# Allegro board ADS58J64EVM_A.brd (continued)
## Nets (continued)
FMC_DIR_CONTROL: J3.H17 U3.15(IO_1_15)
FMC_SCLK: J3.C14 U3.2(IO_1_2/DIFFIO_L1P)
FMC_SDIO: J3.C15 U3.3(IO_1_3/DIFFIO_L1N)
FMC_SDO: J3.D14 U3.4(IO_1_4/DIFFIO_L2P)
FMC_SEN_ADC: J3.D15 U3.5(IO_1_5/DIFFIO_L2N)
FMC_SEN_LMK: J3.G15 U3.6(IO_1_6/DIFFIO_L3P)
FMC_SYSREF_N: C191.1 J3.K38
FMC_SYSREF_P: C190.1 J3.K37
FPGA_JESD_CLKM: C67.2 J3.D5
FPGA_JESD_CLKP: C68.2 J3.D4
FPGA_JESD_SYSREFM: J3.G10 R109.2
FPGA_JESD_SYSREFP: J3.G9 R108.2
FTDI_D5: U3.54(IO_2_54/DIFFIO_R7P) U7.9(D5)
FTDI_D6: U3.53(IO_2_53/DIFFIO_R7N) U7.10(D6)
FTDI_DIR_CONTROL: U3.52(IO_2_52) U7.6(D7)
FTDI_SCLK: U3.61(IO_2_61) U7.1(D0)
FTDI_SDIO: U3.58(IO_2_58/DIFFIO_R5P) U7.5(D1)
FTDI_SDO: U3.57(IO_2_57/DIFFIO_R5N) U7.3(D2)
FTDI_SEN_ADC: U3.56(IO_2_56/DIFFIO_R6P) U7.11(D3)
FTDI_SEN_LMK: U3.55(IO_2_55/DIFFIO_R6N) U7.2(D4)
IOVDD1.15V: C18.1 C19.1 C22.1 C53.1 C170.1 C272.1 C273.1 L3.2 R129.2 TP2.1(TP) U1.4(IOVDD#4) U1.51(IOVDD#51) U1.57(IOVDD#57) U1.64(IOVDD#64) U1.70(IOVDD#70)
JESD_CLKM: C68.1 U5.2(DCLKOUT0N)
JESD_CLKP: C67.1 U5.1(DCLKOUT0P)
JESD_SYSREFM: R108.1 U5.4(SDCLKOUT1N)
JESD_SYSREFP: R109.1 U5.3(SDCLKOUT1P)
LMK_CS: U3.78(IO_2_78/DIFFIO_T9P) U5.18(\\C\S\)
LMK_SCK: U3.77(IO_2_77/DIFFIO_T9N) U5.19(SCK)
LMK_SDIO: R134.2 U3.76(IO_2_76/DIFFIO_T10P) U5.20(SDIO)
LMK_SDO: R113.2 U5.5(RESET)
LMK_SYNC: J10.1(CENTER) R59.1 U5.6(SYNC)
OSCIN_N: C82.2 U5.44(OSCINN)
OSCIN_P: C92.2 C121.2 U5.43(OSCINP)
PDN: JP7.2(PIN2) U1.50(PDN)
RESET: R36.1 SW1.2 U1.48(RESET)
SCAN_EN: R19.2 R20.1 TP20.1(TP) U1.49(SCAN_EN)
SYNCBABM: J3.G13 U1.56(SYNCBABM)
SYNCBABP: J3.G12 U1.55(SYNCBABP)
SYNCBCDM: J3.H32 R185.2
SYNCBCDP: J3.H31 R186.2
SYSREF+: C190.2 R30.2 R133.1 U1.33(SYSREF_P)
SYSREF-: C191.2 R31.2 R133.2 U1.34(SYSREF_M)
SYSREF_N: C72.1 R44.1 U5.14(SDCLKOUT3N)
SYSREF_P: C73.1 R43.1 U5.13(SDCLKOUT3P)
SYSREFM: C73.2 R31.1 R106.1
SYSREFP: C72.2 R30.1 R105.1
T2_1: C141.2 R2.1 R3.1
T2_3: C140.2 R5.2 R6.1
T4_1: C158.2 R8.1 R9.1
T4_3: C157.2 R11.2 R12.1
T7_1: C274.2 R142.1 R144.1
T7_3: C275.2 R141.1 R143.2
T9_1: C203.2 R154.1 R155.1
T9_3: C202.2 R153.1 R156.2
TCK: J15.1 R57.1 U3.24(TCK)
TDI: J15.9 R110.1 U3.23(TDI)
TDO: J15.3 U3.25(TDO)
TMS: J15.5 R111.1 U3.22(TMS)
TRDYAB: J21.1 U1.54(TRDYAB)
TRDYCD: J22.1 U1.1(TRDYCD)
TRIGAB: J23.1 R170.1 U1.53(TRIGAB)
TRIGCD: J24.1 R173.1 U1.2(TRIGCD)
VCPLD1.8V: C155.2 C156.2 C162.2 C165.2 C166.2 C278.1 C279.1 C280.1 C281.1 C282.1 FB17.3 J15.4 JP3.1(PIN1) R110.2 R111.2 TP22.1(TP) U3.9(VCCIO1#9) U3.13(VCCINT#13) U3.31(VCCIO1#31) U3.45(VCCIO1#45) U3.63(VCCINT#63)
VSNS: R115.1 R117.1 U8.6(VSENSE)
N16275326: C10.2 T3.2(SECONDARY) T3.5(PRIMARY)
N16275564: C11.2 T4.2(SECONDARY) T4.5(PRIMARY)
N16918679: C81.2 C84.2 C85.2 C90.2 FB12.1 Y1.6(VDD)
N16918713: R78.2 R87.1 R88.1 Y1.5(OUT_P)
N16918734: R71.1 R73.2 R74.1 Y1.4(OUT_N)
N16918766: FB12.2 JP2.1
N16918796: C80.1 R71.2
N16918798: C80.2 C82.1 R77.1
N16918863: C92.1 C169.2 R61.2 R102.1
N16918987: SJP1.2(PIN2) Y1.2(NC)
N16974113: R113.1 U3.81(IO_2_81/DIFFIO_T8N)
N16976956: JP3.2(PIN2) U3.51(IO_1_51/DIFFIO_B10N)
N17045898: C169.1 R88.2
N17135362: C175.1 R104.1
N17316333: R60.2 R61.1
N17990226: C2.1 R3.2 R5.1
N18101124: Q1.4(G) U12.4(GATE)
N18135910: C106.1 C107.1 C108.1 C109.1 C148.1 FB15.1 R45.1 U11.1(OUT1) U11.2(OUT2)
N18153199: C95.1 J13.2(D-) U7.16(USBDM)
N18153225: C91.1 C163.1 FB10.1 R96.2 TP21.1(TP) U7.20(VCC)
N18153227: C99.1 U7.4(VCCIO) U7.17(3V3OUT)
N18153268: C93.1 J13.3(D+) U7.15(USBDP)
N18164060: J13.4(ID) R13.2
N18272382: C137.1 C138.1 C139.1 C182.1 FB14.1 R123.1 U2.1(OUT1) U2.2(OUT2)
N18340257: D2.1(ANODE) R41.2
N18400299: D1.1(ANODE) R91.1
N18433453: R112.2 R114.1 U8.15(EN)
N18433599: C135.1 R52.1 U8.7(COMP)
N18433651: C144.1 R52.2
N18433655: R51.1 U8.8(RT/CLK)
N18433661: C136.1 U8.9(SS/TR)
N18433720: R118.1 U8.14(PWRGD)
N18433762: C124.1 L1.1 U8.10(PH1) U8.11(PH2) U8.12(PH3)
N18433788: C124.2 U8.13(BOOT)
N18529139: J3.C18 R91.2
N18529232: J3.H2 R84.1
N18993446: C8.1 R9.2 R11.1
N19018410: R18.2 SW1.1
N19072087: FB10.2 J13.1(VBUS)
N19596618: D6.1(ANODE) R85.1
N19596621: D5.1(ANODE) R82.1
N19596623: D3.1(ANODE) R86.1
N19596624: R86.2 U5.48(STATUS_LD2)
N19596626: R85.2 U5.31(STATUS_LD1)
N19596640: C88.1 U5.12(LDOBYP2)
N19596641: C87.1 U5.11(LDOBYP1)
N19596650: D4.1(ANODE) R81.1
N19596653: R82.2 U5.59(CLKIN_SEL1)
N19596656: R81.2 U5.58(CLKIN_SEL0)
N19631315: C74.1 C76.1 C150.1 C151.1 FB16.1 U6.1(OUT1) U6.3(SENSE) U6.20(OUT2)
N19631466: C98.1 U6.14(NR)
N19631491: R83.2 U6.8(1P6V)
N19631493: R75.2 U6.11(0P2V)
N19631495: R72.2 U6.12(0P1V)
N19631505: R76.2 U6.10(0P4V)
N19740812: C183.1 U2.6(NR)
N19741196: R125.2 R126.1 U2.5(EN)
N19751506: C49.1 T5.5(GND)
N19764898: C137.2 R124.1 R176.2 U2.3(FB/SNS)
N19785823: C3.2 R63.2
N19785833: C3.1 R101.1
N19786108: C9.2 R107.2
N19786128: C9.1 R119.1
N19791732: C158.1 T4.4(PRIMARY_DOT)
N19791735: C157.1 T4.6(PRIMARY_CT)
N19818342: C123.1 C127.1 C128.1 C129.1 C263.1 FB13.1 R50.1 U10.1(OUT1) U10.2(OUT2)
N19818462: C134.1 U10.6(NR)
N19818472: R161.2 R162.1 U10.5(EN)
N19818541: C129.2 R116.1 R174.2 U10.3(FB/SNS)
N19839460: R28.2 R29.1 U15.1(EN)
N19839464: C195.1 L2.2 R28.1 U15.7(VIN)
N19839484: L4.1 U15.6(SW)
N19839486: C196.1 R33.2 R37.1 U15.4(VOS)
N19839498: C197.1 C198.1 C271.1 L3.1 L4.2 R33.1
N19839502: C196.2 R32.1 R37.2 U15.3(FB)
N19884960: C201.1 R143.1 R144.2
N19885012: C274.1 T7.4(PRIMARY_DOT)
N19885116: C276.2 R145.2
N19885138: C276.1 R146.1
N19885156: C277.2 T6.2(SECONDARY) T6.5(PRIMARY)
N19885198: C200.2 T7.2(SECONDARY) T7.5(PRIMARY)
N19885294: C203.1 T9.4(PRIMARY_DOT)
N19885373: C206.1 R155.2 R156.1
N19885375: C204.2 T8.2(SECONDARY) T8.5(PRIMARY)
N19885421: C205.2 T9.2(SECONDARY) T9.5(PRIMARY)
N19885585: C207.2 R157.2
N19885597: C207.1 R158.1
N19895674: R182.2 R183.1 R186.1 U1.72(SYNCBCDP)
N19895681: R182.1 R184.2 R185.1 U1.71(SYNCBCDM)
N19922962: C141.1 T2.4(PRIMARY_DOT)
N19926392: C4.2 T1.2(SECONDARY) T1.5(PRIMARY)
N19927040: C5.2 T2.2(SECONDARY) T2.5(PRIMARY)
N19928466: C202.1 T9.6(PRIMARY_CT)
N19936516: C140.1 T2.6(PRIMARY_CT)
N19989779: C275.1 T7.6(PRIMARY_CT)
N20022529: R50.2 R174.1
N20035911: R123.2 R176.1
N20038291: C265.1 U9.15(SS)
N20038313: R166.2 R167.1 U9.11(EN)
N20038327: R64.2 R175.1
N20038329: R128.1 R175.2 U9.16(FB/SNS)
N20038355: C115.1 C116.1 C117.1 R64.1 R129.1 U9.1(OUT4) U9.18(OUT1) U9.19(OUT2) U9.20(OUT3)
N20039194: C286.1 U16.6(NR)
N20039222: R177.2 R178.1 U16.5(EN)
N20039339: C283.1 C284.1 C285.1 C287.1 FB17.1 R180.1 U16.1(OUT1) U16.2(OUT2)
N20039347: C287.2 R180.2 R181.1 U16.3(FB/SNS)
N20052215: C290.1 T5.2(PRIMARY)
N20058798: C184.1 R187.2 U9.10(BIAS)
N20074843: C114.1 U11.6(NR)
N20074851: R188.2 R189.1 U11.5(EN)
N20074920: C106.2 R47.2 R48.1 U11.3(FB/SNS)
N20074982: R45.2 R47.1
N195971120: C66.2 R65.1
N195974181: C65.2 R66.1

Pads without a net: J3 A14 A15 A18 A19 A22 A23 A26 A27 A30 A31 A34 A35 A38 A39 B1 B4 B5 B8 B9 B12 B13 B16 B17 B20 B21 B24 B25 B28 B29 B32 B33 B36 B37 B40 C2 C3 C10 C11 C19 C22 C23 C26 C27 C30 C31 C34 C35 C37 C39 D1 D8 D9 D11 D12 D17 D18 D20 D21 D23 D24 D26 D27 D29 D30 D31 D32 D33 D34 D35 D36 D38 D40 E2 E3 E6 E7 E9 E10 E12 E13 E15 E16 E18 E19 E21 E22 E24 E25 E27 E28 E30 E31 E33 E34 E36 E37 E39 F1 F4 F5 F7 F8 F10 F11 F13 F14 F16 F17 F19 F20 F22 F23 F25 F26 F28 F29 F31 F32 F34 F35 F37 F38 F40 G2 G3 G18 G19 G21 G22 G24 G25 G27 G28 G30 G31 G33 G34 G36 G37 G39 H1 H4 H5 H7 H8 H10 H11 H13 H14 H19 H20 H22 H23 H25 H26 H28 H29 H34 H35 H37 H38 H40 J2 J3 J6 J7 J9 J10 J12 J13 J15 J16 J18 J19 J21 J22 J24 J25 J27 J28 J30 J31 J33 J34 J36 J37 J39 K1 K4 K5 K7 K8 K10 K11 K13 K14 K16 K17 K19 K20 K22 K23 K25 K26 K31 K32 K34 K35 K40; J15 6 7 8; NOREF#9 1; NOREF#13 1; NOREF#16 1; NOREF#31 1; NOREF#35 1; NOREF#36 1; NOREF#37 1; T5 1; U1 22 23; U3 12 14 16 17 18 19 20 21 26 27 28 29 30 37 38 39 40 41 42 43 44 47 48 49 50 62 64 66 67 68 69 70 71 72 73 74 75 82 83 84 85 86 87 88 89 90 91 92 95 96 97 98 99 100; U5 7 8 9 22 23 24 25 27 28 29 30 37 38 40 41 49 50 51 52 54 55 56 57 60 61; U6 2 4 5 6 9 17 18 19; U7 8 12 13 14 19 22 23 24 27 28; U9 9; U12 1 3; U15 2

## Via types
v1: diameter 0.457, hole 0.203, TOP to BOTTOM, 602 vias
v2: diameter 0.356, hole 0.152, TOP to BOTTOM, 82 vias
v3: diameter 0.508, hole 0.254, TOP to BOTTOM, 2773 vias
v4: diameter 0.559, hole 0.305, TOP to BOTTOM, 281 vias
v5: diameter 0.762, hole 0.381, TOP to BOTTOM, 8 vias
v6: diameter 0.4, hole 0.203, TOP to BOTTOM, 48 vias

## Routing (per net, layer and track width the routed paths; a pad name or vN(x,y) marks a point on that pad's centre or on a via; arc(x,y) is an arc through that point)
5.0V_IN: length 24.6
  BOTTOM w0.127: Q1.8 19.41,62.61 v4(19.51,62.71) ; v4(20.53,60.72) 20.51,60.74 v4(20.51,61.71) ; v4(20.53,60.72) 20.54,60.71 v4(21.51,60.71) ; v4(20.53,60.72) 19.52,60.72 v4(19.51,60.71) ; v4(20.53,60.72) 20.53,59.73 v4(20.51,59.71) ; v4(21.51,60.71) v4(21.51,59.71) ; v4(21.51,60.71) v4(21.51,61.71) ; v4(19.51,62.71) v4(19.51,61.71) ; v4(19.51,62.71) v4(20.51,62.71) ; v4(21.51,59.71) v4(20.51,59.71) ; v4(21.51,59.71) v4(21.51,58.71) v4(20.51,58.71) ; v4(19.51,61.71) v4(20.51,61.71) ; v4(19.51,61.71) v4(19.51,60.71) ; v4(20.51,58.71) v4(19.51,58.71) ; v4(20.51,58.71) v4(20.51,59.71) ; v4(19.51,58.71) v4(19.51,59.71) ; v4(19.51,58.71) 19.41,58.8 Q1.5 ; v4(21.51,61.71) v4(20.51,61.71) ; v4(21.51,61.71) v4(21.51,62.71) v4(20.51,62.71) ; v4(20.51,61.71) v4(20.51,62.71) ; v4(20.51,59.71) v4(19.51,59.71) ; v4(19.51,59.71) v4(19.51,60.71)
5VIN: length 6
  TOP w0.254: U8.16 8.99,90.89 v3(8.75,90.65)
  TOP w0.305: v4(8.69,73.23) 8.85,73.06 U6.16 ; v3(9.8,88.87) 10.34,89.41 U8.2 ; U6.15 7.34,74.16 v4(6.4,73.23)
  TOP w0.356: U6.13 v3(6.58,75.46)
  vias: v3(5.74,93.45) v3(5.82,89.1) v3(5.82,87.83) v3(5.82,86.44) v3(5.82,85.17) v3(5.82,83.9) v3(6.71,88.47) v3(6.71,87.07) v3(6.71,85.8) v3(6.71,84.53) v3(6.71,83.26) v3(7.34,90.25) v3(7.85,88.72) v3(7.85,87.45) v3(7.85,86.31) v3(7.9,84.81) v3(7.9,83.29) v3(8.66,84.05) v3(8.74,89.36) v3(8.74,85.67) v3(8.99,86.82) v3(9.12,88.09) v3(9.3,84.81) v3(9.3,83.29) v3(9.84,90.45) v3(10.13,87.83) v3(10.08,86.72) v3(10.08,85.57) v3(20.88,41.22) v3(20.88,40.08) v3(20.88,39.07) v3(22.22,41.15) v3(22.22,40.01) v3(22.22,38.99) v3(23.49,41.15) v3(23.49,40.01) v3(23.49,38.99) v4(6.4,72.09) v4(6.4,70.94) v4(7.54,73.23) v4(7.54,72.09) v4(7.54,70.94) v4(8.69,72.09) v4(8.69,70.94) v4(23.52,64.9) v4(23.52,63.63) v4(23.52,62.36) v4(23.52,61.21) v4(23.52,60.07) v4(24.64,64.9) v4(24.64,63.63) v4(24.64,62.36) v4(24.64,61.21) v4(24.64,60.07) v4(25.91,62.36) v4(25.91,61.21) v4(25.91,60.07) v4(27.05,62.36) v4(27.05,61.21) v4(27.05,60.07) v4(28.19,62.36) v4(28.19,61.21) v4(28.19,60.07) v4(31.06,75.23) v4(31.06,73.96) v4(31.06,72.69) v4(31.06,71.55) v4(31.09,70.38) v4(32.18,75.23) v4(32.18,73.96) v4(32.18,72.69) v4(32.18,71.55) v4(32.21,70.38)
+2.5V: length 19.1
  TOP w0.305: v3(37.56,64.48) v3(35.46,64.48) 35.12,64.48 35.03,64.39 35.59,63.83 37.56,63.83 ; U9.5 56.88,81.34 C185.1 ; v3(31.9,96.56) v3(29.79,96.56) 29.45,96.56 29.36,96.47 C126.1 29.92,95.91 31.9,95.91 ; U2.8 28.02,87.5 C288.1 27.55,88.15 v3(27.89,88.15) v3(29.99,88.15) ; U11.7 30.69,106.61 v3(30.6,106.52)
  vias: v3(9.07,107.11) v3(9.07,105.97) v3(10.57,107.11) v3(10.57,105.97) v3(12.01,107.09) v3(12.01,105.94) v3(15.67,87.6) v3(16.66,99.87) v3(16.69,102.16) v3(16.69,101.02) v3(17.65,102.16) v3(17.65,101.02) v3(17.63,99.87) v3(18.64,102.13) v3(18.64,100.99) v3(18.62,99.85) v3(19.66,99.87) v3(19.68,102.16) v3(19.68,101.02) v3(20.68,99.87) v3(20.7,102.16) v3(20.7,101.02) v3(21.67,102.16) v3(21.67,101.02) v3(21.64,99.87) v3(26.8,88.16) v3(26.8,87.02) v3(26.8,85.83) v3(27.86,85.83) v3(27.89,87.02) v3(28.7,96.57) v3(28.7,95.43) v3(28.7,94.23) v3(28.93,88.1) v3(28.93,86.97) v3(28.91,85.83) v3(29.4,106.52) v3(29.4,105.45) v3(29.4,104.41) v3(29.4,103.34) v3(29.77,94.23) v3(29.79,95.43) v3(29.97,85.83) v3(30,87.02) v3(30.55,104.38) v3(30.6,105.43) v3(30.6,103.32) v3(30.83,96.51) v3(30.84,95.38) v3(30.81,94.23) v3(31.73,105.43) v3(31.68,104.39) v3(31.7,103.33) v3(31.9,95.43) v3(31.88,94.23) v3(34.37,64.49) v3(34.37,63.35) v3(34.37,62.15) v3(35.46,63.35) v3(35.43,62.15) v3(36.47,62.15) v3(36.5,64.43) v3(36.5,63.3) v3(37.57,63.35) v3(37.54,62.15) v3(47.55,81.46) v3(51.77,85.9) v3(53.52,84.76) v3(53.52,83.62) v3(53.52,82.42) v3(54.61,84.75) v3(54.61,83.62) v3(54.58,82.42) v3(55.65,84.7) v3(55.65,83.57) v3(55.63,82.42) v3(56.72,84.75) v3(56.72,83.62) v3(56.69,82.42)
+3.3VCLK: length 10.3
  TOP w0.305: v3(48.69,44.4) 48.39,44.1 U3.94
  TOP w0.318: v3(41.49,44.36) 41.41,44.02 41.39,44.01 41.39,42.77 U3.80 ; U3.59 v3(39.1,52.47)
  TOP w0.508: R134.1 75.95,59.69 v3(75.44,60.2)
  BOTTOM w0.508: C153.2 v3(48.69,45.03) ; C152.2 v3(41.48,45.09) ; v3(39.1,52.47) v3(39.1,53.14)
  vias: v3(20.75,73.3) v3(20.75,70.92) v3(20.78,75.69) v3(20.83,74.52) v3(22.33,75.72) v3(22.35,74.52) v3(22.63,73.33) v3(22.73,70.92) v3(23.77,75.74) v3(23.8,74.57) v3(23.85,73.33) v3(23.88,72.14) v3(23.83,70.92) v3(25.07,74.57) v3(25.07,70.94) v3(25.1,75.74) v3(25.12,73.33) v3(25.1,72.16) v3(73.56,51.87) v3(73.53,50.62) v3(73.79,62.87) v3(73.79,60.2) v3(73.79,57.53) v3(74.55,62.74) v3(74.55,51.87) v3(74.55,50.65) v3(74.93,59.82) v3(75.06,57.02) v3(75.44,62.87) v3(75.44,57.53) v3(75.51,51.84) v3(75.49,50.65) v3(75.82,63.5) v3(75.82,58.17) v3(96.06,66) v3(96.6,65.19) v3(97.13,66) v3(98.22,65.35) v3(100.71,44.95) v3(100.71,40.28) v3(101.78,55.02) v3(101.96,56.41) v3(102.57,55.63) v3(103.05,56.46) v3(103.4,55.25) v3(104.29,55.68) v3(105,52.3) v3(105,51.26) v3(105.05,50.27) v3(105.05,49.23) v3(106.02,52.32) v3(106.02,51.26) v3(106.07,50.29) v3(106.07,49.23) v3(120.32,41.34)
AVDD1.9V: length 96.5
  TOP w0.241: v1(105.89,85.09) 106.25,85.09 v2(106.43,84.91) v2(106.99,84.91) ; v1(117.98,85.14) 117.5,85.14 v2(117.39,85.03) 117.27,84.91 v2(116.79,84.91) ; v1(105.89,81.58) 106.21,81.58 v2(106.46,81.83) 106.47,81.83 106.55,81.91 U1.45 v2(107.01,81.91) ; v1(109.98,87.66) 110.13,87.5 v2(110.13,87.12) v2(110.13,86.56) ; v1(113.77,87.66) 113.64,87.53 v2(113.64,86.56)
  TOP w0.254: v2(116.79,81.91) 117.29,81.91 117.53,82.14 v1(117.98,82.14)
  L3-PWR1 w0.508: JP7.1 167.23,79.88 170.15,76.96 170.15,72.92 165.15,67.92 v1(162.28,67.92)
  L6-PWR2 w0.127: v1(105.89,81.58) 106.22,81.58 106.55,81.91 106.56,81.91 v2(107.01,81.91)
  L6-PWR2 w0.508: 100.66,81.74 100.66,80.67 99.92,79.93 v1(98.32,79.93) ; v1(119.74,80.04) 122.07,80.04 ; 122.07,80.04 155.88,80.04 158.78,82.93 164.08,82.93 JP7.1 ; 122.07,80.04 122.1,80.01 122.1,78.41 121.51,77.83 121.51,75.97 120.6,75.06 119.56,75.06 v1(118.01,73.51)
  BOTTOM w0.254: v1(109.98,87.66) 110.13,87.5 v2(110.13,87.12) v2(110.13,86.56) ; v2(107.01,81.91) 106.54,81.91 v2(106.46,81.83) 106.21,81.58 v1(105.89,81.58) ; v1(117.98,82.14) 117.53,82.14 v2(117.38,81.99) 116.87,81.99 v2(116.79,81.91) ; v1(105.89,85.09) 106.07,84.91 v2(106.43,84.91) v2(106.99,84.91) ; v2(113.64,86.56) 113.64,86.57 v2(113.64,87.13) 113.77,87.25 v1(113.77,87.66) ; v2(116.79,84.91) 117.27,84.91 v2(117.39,85.03) 117.5,85.14 v1(117.98,85.14)
  vias: v1(44.7,108.51) v1(44.73,107.42) v1(44.73,106.4) v1(44.73,105.38) v1(44.73,104.37) v1(44.73,103.35) v1(45.72,108.51) v1(45.75,107.42) v1(45.75,106.4) v1(45.75,105.38) v1(45.75,104.37) v1(45.75,103.35) v1(46.74,108.51) v1(46.81,107.39) v1(46.81,106.38) v1(47.75,108.51) v1(47.83,107.39) v1(47.83,106.38) v1(48.77,108.51) v1(48.84,107.39) v1(48.84,106.38)
AVDD1.15V: length 31.4
  TOP w0.241: v1(105.89,85.7) 106.32,85.7 106.61,85.41 v2(106.99,85.41) ; v2(115.64,86.56) v2(115.64,87.21) v1(116.01,87.59) ; v2(117.37,82.91) v2(116.79,82.91) ; v2(106.99,82.91) 106,82.91 v1(105.89,82.8) ; v1(105.89,82.19) 106.2,82.19 v2(106.41,82.41) v2(106.99,82.41) ; v2(116.79,81.41) 117.43,81.41 ; v2(108.14,86.56) v2(108.14,87.16) v1(107.71,87.59) ; v2(116.79,85.41) 117.16,85.41 117.5,85.75 v1(117.98,85.75) ; v1(113.03,87.66) 113.14,87.55 v2(113.14,86.56) ; v1(110.74,87.66) 110.64,87.55 v2(110.64,86.56) ; v1(105.89,80.98) 106.2,80.98 106.63,81.41 v2(106.99,81.41) ; v2(116.79,84.41) 117.86,84.41 v1(117.98,84.53) ; v2(106.99,84.41) 105.96,84.41 v1(105.89,84.48)
  TOP w0.254: v1(117.98,82.75) 117.83,82.91 v2(117.37,82.91) ; v1(117.98,81.53) 117.56,81.53 v2(117.43,81.41) 117.43,81.41
  BOTTOM w0.254: v1(117.98,85.75) 117.51,85.75 v2(117.38,85.62) 117,85.62 v2(116.79,85.41) ; v2(116.79,84.41) 116.79,84.4 v2(117.38,84.4) 117.86,84.4 v1(117.98,84.53) ; v1(105.89,84.48) 105.96,84.41 v2(106.42,84.41) 106.42,84.41 v2(106.99,84.41) ; v2(110.64,86.56) 110.64,87.12 v2(110.63,87.13) 110.63,87.54 v1(110.74,87.66) ; v2(116.79,82.91) 117.37,82.91 v2(117.37,82.91) 117.82,82.91 v1(117.98,82.75) ; v2(106.99,82.41) v2(106.41,82.41) 106.11,82.41 v1(105.89,82.19) ; v2(106.99,82.91) 106.43,82.91 v2(106.42,82.9) 105.99,82.9 v1(105.89,82.8) ; v2(113.14,86.56) 113.14,87.15 v2(113.13,87.16) 113.13,87.55 v1(113.03,87.66) ; v2(108.14,86.56) v2(108.14,87.16) v1(107.71,87.59) ; v2(106.99,81.41) 106.65,81.41 106.22,80.98 v1(105.89,80.98) ; v1(117.98,81.53) 117.56,81.53 v2(117.43,81.41) 117.43,81.41 v2(116.79,81.41) ; v1(105.89,85.7) 106.32,85.7 v2(106.42,85.6) 106.8,85.6 v2(106.99,85.41) ; v1(116.01,87.59) v2(115.64,87.21) v2(115.64,86.56)
  vias: v1(43.18,97.71) v1(43.18,96.67) v1(43.18,95.53) v1(43.21,94.34) v1(43.18,93.17) v1(44.12,97.71) v1(44.12,96.67) v1(44.12,95.53) v1(45.36,97.69) v1(45.36,96.65) v1(45.36,95.5) v1(46.3,97.69) v1(46.3,96.65) v1(46.3,95.5) v1(47.35,97.69) v1(47.35,96.65) v1(47.35,95.5) v1(47.35,94.34) v1(47.35,93.19) v1(48.29,97.69) v1(48.29,96.65) v1(48.29,95.5) v1(48.29,94.34) v1(48.29,93.19) v2(106.42,81.21)
GND: length 170.7
  TOP w0.241: v1(110.11,75.69) 110.14,75.72 v1(110.14,76.23) v2(110.14,76.76) ; v1(113.66,75.69) 113.64,75.72 v1(113.64,76.23) v2(113.64,76.76) ; v2(111.64,76.76) v2(111.63,76.33)
  TOP w0.254: v2(111.14,86.56) v2(111.14,87.14) ; v2(115.14,86.56) v2(115.14,87.15) ; v2(109.64,86.56) v2(109.65,87.12) ; v2(106.53,78.41) v2(106.99,78.41) ; v2(112.64,86.56) v2(112.65,87.12)
  TOP w0.305: v3(38.79,49.48) U3.65 v3(36.6,49.48) ; v3(113.74,72.57) 113.63,72.68 113.63,75.66 v1(113.66,75.69) ; v3(48.39,56.97) U3.32 v3(48.39,59.38) 48.39,59.39 ; v4(33.88,97.64) 34.25,98.01 U10.4 ; 118.03,77.87 117.49,78.41 v2(117.27,78.41) v2(116.79,78.41) ; 115.44,73.59 116.18,72.85 v3(116.18,72.59) ; v3(54.38,49.5) 54.35,49.47 U3.11 51.73,49.47 v3(51.56,49.3) ; v3(39.01,51.69) 38.73,51.97 U3.60 v3(36.6,51.97) ; 33.05,95.73 v3(33.05,94.84) ; v1(110.11,75.69) 110.11,70.28 v3(110.52,69.88) ; U3.10 54.33,48.97 v3(54.38,48.92) ; v3(40.89,41.41) U3.79 40.89,43.92 v3(40.46,44.35) ; U8.4 11.34,90.03 v3(11.1,89.79) 10.84,90.05 U8.3 ; v4(39.54,65.62) 39.92,66 U16.4 ; U6.7 v3(10.91,78.75) ; 32.87,108.33 32.87,108.81 32.64,109.04 C114.2 33.3,110.06 33.48,109.88 33.48,108.51 ; C22.2 v3(111.86,73.51) ; v3(51.92,44.37) 52.01,44.47 U3.1 53.88,44.47 v3(54.23,44.12) ; U9.12 v3(50,80.69) ; 33.05,98.43 33.05,98.91 32.66,99.29 C134.2 32.74,100.05 33.35,100.05 33.71,99.69 33.71,98.32 ; 33.71,95.73 v3(33.71,94.84) ; 31.14,90.02 31.14,91.19 C183.2 31.52,91.41 31.78,91.16 31.78,90.14 ; v3(41.4,59.36) U3.46 41.39,56.73 v3(41.17,56.52) ; 12.19,91.3 v3(12.19,90.98) ; v2(106.53,78.41) 106.53,78.41 105.67,78.41 105.41,78.66 ; U9.3 v3(56.77,80.04) ; v4(31.97,89.08) 32.34,89.45 U2.4 ; U9.2 v3(56.78,79.39) ; v4(33.67,107.53) 34.05,107.91 U11.4 ; 38.68,63.63 v3(38.68,62.94) ; v3(47.68,44.27) 47.89,44.06 U3.93 v3(47.89,41.41) ; U9.17 v3(52.72,76.69) ; 39.4,66.37 39.4,67.72 38.94,68.17 38.4,68.17 C286.2 38.33,67.31 38.73,66.9 38.73,66.37 ; v1(118.36,78.92) 118.36,78.41 118.38,78.4 ; 39.37,63.6 v3(39.37,62.87) ; 31.14,87.1 v3(31.14,86.26) ; U9.4 v3(56.73,80.69) ; 31.8,87.05 v3(31.8,86.26)
  TOP w0.356: U9.14 49.57,79.39 v3(49.2,79.76) 49.48,80.04 U9.13
  TOP w0.508: 105.83,63.71 106.08,63.71 106.81,62.97 107.58,62.97 v3(107.82,63.22) ; 42.44,76.84 42.44,77.57 v3(42.11,77.9) ; v3(41.07,77.93) 41.2,77.8 C197.2
  BOTTOM w0.254: v2(116.79,78.41) v2(117.27,78.41)
  BOTTOM w0.305: v3(38.33,78.54) U15.5 37.84,78.04 v3(38.22,77.66) ; v3(48.39,56.97) 48.11,56.69 C165.1 48.11,56.54 v3(48.36,56.29)
  BOTTOM w0.356: v3(22.79,48.09) U7.21 24.71,48.09 v3(24.71,48.08) ; v3(24.74,50.7) 24.73,50.69 U7.25 22.72,50.69 v3(22.71,50.67) ; v3(32.05,48.74) U7.7 v3(29.82,48.72) ; U7.18 22.79,46.14 v3(22.78,46.13) ; v3(22.71,51.36) 22.73,51.34 U7.26 24.71,51.34 v3(24.71,51.33)
  BOTTOM w0.508: J3.B7 J3.A8 J3.A9 ; J3.A9 J3.B10 J3.B11 149.1,8.76 v1(147.83,8.76) 146.56,10.03 J3.B15 v1(144.02,8.76) ; J3.A9 v1(152.3,8.15) ; v1(142.75,13.84) v1(144.02,12.57) J3.C16 v1(142.75,11.3) v1(141.48,10.03) ; v1(142.75,13.84) v1(141.48,15.11) v1(142.75,16.38) ; v1(142.75,13.84) v1(143.33,14.43) ; v1(157.99,16.38) 156.72,17.65 v1(157.99,18.92) ; 156.72,20.19 156.79,20.19 v3(157.51,20.9) ; v1(133.86,20.19) 133.86,20.17 v1(133.32,19.63) ; J3.J23 v1(135.13,18.87) v1(134.57,18.31) ; C164.2 v3(88.75,52.45) ; v3(150.32,21.41) 149.1,20.19 v1(150.37,18.92) 149.1,17.65 v1(150.37,16.38) 149.1,15.11 v1(150.37,13.84) 151.64,12.57 ; v1(137.67,15.11) 138.94,16.38 v1(137.67,17.65) v1(138.94,18.92) v1(137.67,20.19) 137.69,20.19 v3(138.51,21.01) ; C88.2 86.11,61.85 v3(86.49,61.47) ; J3.G8 v1(152.91,17.65) ; 149.1,11.3 v1(147.83,11.3) ; 156.72,15.11 v1(157.99,13.84) 156.72,12.57 ; J3.B3 v1(159.26,11.3) ; v1(141.48,17.65) v1(142.75,18.92) ; v1(152.91,15.11) J3.E8 155.45,12.57 ; J3.J8 v1(152.91,20.19) ; 156.72,10.03 v1(157.99,11.3) ; v1(152.91,11.3) J3.C8 ; C87.2 v3(87.5,61.47) ; J3.B2 v1(163.07,8.76)
  vias: v1(86.61,69.09) v1(90.04,69.09) v1(99.69,81.03) v1(105.28,85.7) v1(105.28,85.09) v1(105.28,84.48) v1(105.28,82.8) v1(105.28,82.19) v1(105.28,81.58) v1(105.28,80.98) v1(105.28,80.37) v1(105.46,78.89) v1(107.28,88.02) v1(108.43,75.03) v1(109.98,88.27) v1(110.74,88.27) v1(113.03,88.27) v1(113.54,18.92) v1(113.54,16.38) v1(113.54,13.84) v1(113.54,11.3) v1(113.54,8.76) v1(113.77,88.27) v1(114.81,20.19) v1(114.81,17.65) v1(114.81,15.11) v1(114.81,12.57) v1(114.81,10.03) v1(115.32,75.11) v1(116.13,73.51) v1(116.08,18.92) v1(116.08,16.38) v1(116.08,13.84) v1(116.08,11.3) v1(116.08,10.03) v1(116.45,88.02) v1(117.35,12.57) v1(117.35,8.76) v1(118.59,85.75) v1(118.59,85.14) v1(118.59,84.53) v1(118.59,82.75) v1(118.59,82.14) v1(118.59,81.53) v1(118.59,80.92) v1(118.62,20.19) v1(118.62,17.65) v1(118.62,15.11) v1(118.62,11.3) v1(118.62,8.76) v1(119.89,18.92) v1(119.89,16.38) v1(119.89,13.84) v1(119.89,10.03) v1(121.16,10.03) v1(122.43,20.19) v1(122.43,17.65) v1(122.43,15.11) v1(122.43,11.3) v1(122.43,8.76) v1(123.7,18.92) v1(123.7,16.38) v1(123.7,13.84) v1(123.7,11.3) v1(123.7,8.76) v1(124.97,10.03) v1(126.24,20.19) v1(126.24,17.65) v1(126.24,15.11) v1(126.24,10.03) v1(127.51,18.92) v1(127.51,16.38) v1(127.51,13.84) v1(127.51,11.3) v1(127.51,8.76) v1(128.78,12.57) v1(128.78,11.3) v1(128.78,8.76) v1(130.05,20.19) v1(130.05,17.65) v1(130.05,15.11) v1(130.05,10.03) v1(131.32,18.92) v1(131.32,16.38) v1(131.32,13.84) v1(131.32,10.03) v1(132.38,82.68) v1(132.59,12.57) v1(132.59,11.3) v1(132.59,8.76) v1(133.86,17.65) v1(133.86,15.11) v1(133.86,11.3) v1(133.86,8.76) v1(135.13,16.38) v1(135.13,13.84) v1(135.13,10.03) v1(136.4,12.57) v1(136.4,10.03) v1(136.68,84.68) v1(137.67,11.3) v1(137.67,8.76) v1(138.94,13.84) v1(138.94,11.3) v1(138.94,8.76) v1(140.21,12.57) v1(140.21,10.03) v1(141.48,20.19) v1(142.75,8.76) v1(145.29,20.19) v1(145.29,17.65) v1(145.29,15.11) v1(146.56,18.92) v1(146.56,16.38) v1(146.56,13.84) v1(147.83,12.57) v1(149.79,8.38) v1(151,9) v1(151.77,8.06) v1(154.93,8.32) v1(155.09,11.88) v1(156.08,11.04) v1(156.08,9.14) v1(157.25,8.33) v1(157.29,11.69) v1(157.28,9.24) v1(157.99,8.76) v1(159.26,18.92) v1(159.26,16.38) v1(159.26,13.84) v1(159.26,8.76) v1(160.08,8.26) v1(160.53,20.19) v1(160.53,17.65) v1(160.53,15.11) v1(160.53,12.57) v1(161.16,8.4) v1(161.8,20.19) v1(161.8,15.11) v1(161.8,12.57) v1(162.28,8.26) v1(163.07,18.92) v1(163.07,16.38) v1(163.07,13.84) v1(163.07,11.3) v2(117.73,78.18) v3(0.64,112.4) v3(0.64,109.85) v3(0.64,107.31) v3(0.64,104.78) v3(0.64,102.24) v3(0.64,99.69) v3(0.64,97.16) v3(0.64,94.62) v3(0.64,92.08) v3(0.64,89.53) v3(0.64,87) v3(0.64,84.46) v3(0.64,81.91) v3(0.66,46.69) v3(0.66,44.15) v3(0.66,41.61) v3(0.66,39.07) v3(0.69,79.45) v3(0.69,76.91) v3(0.69,74.37) v3(0.69,71.83) v3(0.69,69.29) v3(0.69,66.75) v3(0.69,64.21) v3(0.69,61.67) v3(0.69,59.13) v3(0.69,56.59) v3(0.69,54.05) v3(0.69,51.51) v3(0.69,48.97) v3(1.52,40.13) v3(1.52,38.86) v3(1.65,49.02) v3(1.65,47.75) v3(1.91,113.03) v3(2.38,39.5) v3(2.51,48.39) v3(2.54,43.87) v3(2.67,94.49) v3(2.67,91.95) v3(2.67,89.41) v3(2.67,86.87) v3(2.74,84.53) v3(3.3,40.13) v3(3.3,38.86) v3(3.43,49.02) v3(3.43,47.75) v3(3.56,61.7) v3(3.56,59.13) v3(3.53,56.85) v3(3.81,113.03) v3(3.81,54.64) v3(3.84,50.47) v3(3.94,104.65) v3(3.94,102.11) v3(3.94,99.57) v3(3.94,97.03) v3(3.94,81.79) v3(3.94,79.25) v3(3.89,74.81) v3(3.94,72.9) v3(3.94,70.36) v3(4.67,77.37) v3(4.67,76.23) v3(5.08,43.87) v3(5.21,52.58) v3(5.31,106.83) v3(5.77,90.23) v3(6.35,113.03) v3(6.35,69.34) v3(6.35,54.64) v3(6.38,50.47) v3(6.48,104.65) v3(6.48,102.11) v3(6.48,99.57) v3(6.48,97.03) v3(6.48,81.79) v3(6.48,79.25) v3(6.88,41.12) v3(6.96,38.02) v3(7.11,49.02) v3(7.11,47.75) v3(7.16,42.34) v3(7.11,40.13) v3(7.11,38.86) v3(7.54,94.72) v3(7.75,111) v3(7.75,108.46) v3(7.87,77.85) v3(7.97,48.39) v3(7.97,39.49) v3(8.08,42.34) v3(8.76,51.31) v3(8.76,40.13) v3(8.76,38.86) v3(8.89,113.03) v3(8.96,80.8) v3(8.89,49.02) v3(8.89,47.75) v3(9.02,103.38) v3(9.02,100.84) v3(9.02,42.34) v3(9.4,69.34) v3(9.42,41.12) v3(9.5,38.02) v3(9.6,81.84) v3(10.13,92.51) v3(10.13,91.59) v3(10.26,80.8) v3(10.29,111) v3(10.29,108.46) v3(10.36,71.68) v3(10.29,36.07) v3(10.29,33.53) v3(10.59,92.05) v3(10.82,70.92) v3(11.05,92.51) v3(11.05,91.59) v3(11.07,84.94) v3(11.07,83.16) v3(11.13,90.73) v3(11.18,40.87) v3(11.13,38.86) v3(11.3,51.31) v3(11.38,88.87) v3(11.56,103.38) v3(11.56,100.84) v3(11.73,87.35) v3(11.71,84.05) v3(12.07,113.03) v3(12.12,86.84) v3(12.34,84.81) v3(12.34,83.29) v3(12.32,67.69) v3(12.47,77.85) v3(12.57,93.78) v3(12.5,86.33) v3(12.57,79.96) v3(12.6,88.82) v3(12.83,111) v3(12.83,108.46) v3(12.83,50.04) v3(12.83,47.5) v3(12.83,36.07) v3(12.83,33.53) v3(13.06,69.95) v3(13.06,69.24) v3(13.97,113.03) v3(14.1,103.38) v3(14.1,100.84) v3(14.1,98.3) v3(14.1,84.33) v3(14.1,81.79) v3(14.3,38.84) v3(14.86,68.96) v3(14.86,67.84) v3(15.16,78.71) v3(15.37,111) v3(15.37,108.46) v3(15.37,97.03) v3(15.37,52.58) v3(15.37,50.04) v3(15.28,47.58) v3(15.37,36.07) v3(15.37,33.53) v3(15.39,54.64) v3(15.57,95.22) v3(15.57,93.7) v3(15.67,89.15) v3(15.72,68.3) v3(15.93,40.18) v3(15.95,38.89) v3(16.05,79.35) v3(16.51,113.03) v3(16.51,68.96) v3(16.51,67.84) v3(16.64,105.92) v3(16.64,103.38) v3(16.64,84.33) v3(16.64,81.79) v3(16.76,39.5) v3(16.79,97.23) v3(17.09,92.18) v3(17.09,90.65) v3(17.63,40.23) v3(17.65,38.79) v3(17.68,97.23) v3(17.91,111) v3(17.91,108.46) v3(17.91,67.82) v3(17.93,54.64) v3(17.91,52.58) v3(17.91,50.04) v3(17.91,36.07) v3(17.91,33.53) v3(18.64,97.23) v3(19.05,113.03) v3(19.18,105.92) v3(19.18,103.38) v3(19.18,91.95) v3(19.18,89.41) v3(19.18,86.87) v3(19.18,84.33) v3(19.18,80.52) v3(19.18,77.98) v3(19.24,72.46) v3(19.24,69.54) v3(19.47,67.03) v3(19.44,45.5) v3(19.42,43.48) v3(19.66,97.23) v3(20.45,111) v3(20.45,108.46) v3(20.45,67.82) v3(20.45,54.53) v3(20.45,52.58) v3(20.45,50.04) v3(20.45,36.07) v3(20.45,33.53) v3(20.65,81.58) v3(20.62,80.47) v3(20.8,97.23) v3(21.51,81.03) v3(21.56,42.98) v3(21.59,45.97) v3(21.72,95.76) v3(21.72,91.95) v3(21.72,89.41) v3(21.72,86.87) v3(21.72,84.33) v3(21.72,69.34) v3(21.77,48.45) v3(21.82,97.23) v3(22.22,113.03) v3(22.38,81.58) v3(22.4,80.49) v3(22.45,56.87) v3(22.43,55.96) v3(22.99,111) v3(22.99,108.46) v3(23.06,105.92) v3(22.99,67.82) v3(22.99,54.53) v3(22.99,36.07) v3(22.99,33.53) v3(23.93,79.43) v3(24.13,113.03) v3(24.14,91.94) v3(24.26,97.03) v3(24.26,94.49) v3(24.36,84.33) v3(24.33,81.38) v3(24.5,87.02) v3(24.54,69.42) v3(24.66,79.91) v3(24.89,104.01) v3(25.11,46.38) v3(25.09,44.77) v3(25.53,111) v3(25.53,108.46) v3(25.53,105.92) v3(25.53,89.41) v3(25.53,83.06) v3(25.53,67.82) v3(25.53,55.12) v3(25.53,42.42) v3(25.53,39.88) v3(25.53,36.07) v3(25.53,33.53) v3(25.65,57.96) v3(25.6,56.9) v3(25.76,78.87) v3(25.9,47.01) v3(26.26,45.02) v3(26.43,51.41) v3(26.49,76.86) v3(26.54,58.52) v3(26.67,113.03) v3(26.68,91.94) v3(26.59,57.48) v3(26.75,47.86) v3(26.8,102.11) v3(26.8,99.57) v3(26.8,97.03) v3(26.8,94.49) v3(27.05,90.35) v3(27,89.41) v3(27,74.98) v3(27.08,71.78) v3(27.08,69.44) v3(27.2,45.9) v3(27.53,57.99) v3(27.56,56.9) v3(27.56,49.32) v3(27.81,89.87) v3(28.07,111) v3(28.07,108.64) v3(27.99,105.92) v3(28.07,83.06) v3(28.07,80.52) v3(28.07,55.12) v3(28.07,52.58) v3(28.07,42.42) v3(28.07,39.88) v3(28.07,36.07) v3(28.07,33.53) v3(28.1,77.64) v3(28.6,47.52) v3(28.96,107.8) v3(28.91,97.84) v3(29.08,98.65) v3(29.16,44.73) v3(29.21,113.03) v3(29.34,102.11) v3(29.34,99.57) v3(29.49,108.64) v3(29.84,98.15) v3(29.97,65.1) v3(29.95,64.34) v3(30.61,83.06) v3(30.61,80.52) v3(30.59,77.7) v3(30.61,55.12) v3(30.61,42.42) v3(30.61,39.88) v3(30.61,36.07) v3(30.61,33.53) v3(30.89,111.28) v3(31.06,65.1) v3(31.06,64.34) v3(31.5,113.03) v3(32.05,76.78) v3(32.84,55.22) v3(33.02,104.67) v3(33.02,102.13) v3(33.13,83.13) v3(33.16,80.59) v3(33.15,57.66) v3(33.15,44.96) v3(33.15,42.42) v3(33.15,38.61) v3(33.15,36.07) v3(33.15,33.53) v3(33.4,113.03) v3(33.51,91.88) v3(33.66,84.76) v3(33.76,76.78) v3(33.87,111.24) v3(33.78,69.6) v3(33.88,78.49) v3(34.24,104.24) v3(34.49,66.55) v3(34.65,94.36) v3(34.93,65.86) v3(35.18,67.82) v3(35.31,66.57) v3(35.61,82.52) v3(35.59,80.82) v3(35.63,48.13) v3(35.69,102.11) v3(35.69,99.57) v3(35.69,60.2) v3(35.69,57.66) v3(35.69,44.96) v3(35.69,38.61) v3(35.69,36.07) v3(35.69,33.53) v3(35.94,113.03) v3(35.89,89.41) v3(36.05,91.88) v3(36.35,90.12) v3(36.96,111) v3(37.02,84.19) v3(37.11,89.79) v3(37.34,42.44) v3(37.57,107.57) v3(37.8,59.23) v3(37.92,110.29) v3(37.95,109.25) v3(38.02,97.74) v3(38.07,76.3) v3(38.07,75.21) v3(38.23,86.92) v3(38.23,85.42) v3(38.23,38.61) v3(38.23,36.07) v3(38.23,33.53) v3(38.35,98.37) v3(38.38,99.39) v3(38.48,113.03) v3(38.79,108) v3(38.89,109.75) v3(38.96,79.73) v3(38.94,76.3) v3(38.91,75.18) v3(39.07,86.94) v3(39.07,85.39) v3(38.99,69.6) v3(39.14,103.63) v3(39.14,101.09) v3(39.24,98.04) v3(39.37,60.96) v3(39.65,45.47) v3(39.85,110.29) v3(39.93,108.59) v3(40.06,98.37) v3(40.13,52.45) v3(40.23,99.39) v3(40.21,91.71) v3(40.23,90.6) v3(40.26,50.42) v3(40.77,111) v3(40.69,108.1) v3(40.77,55.12) v3(40.77,47.5) v3(40.72,38) v3(40.77,36.07) v3(40.77,33.53) v3(41.02,90.07) v3(41.1,98.07) v3(41.28,95.1) v3(41.28,93.55) v3(41.2,91.14) v3(41.25,61.98) v3(41.36,67.54) v3(41.66,113.03) v3(41.68,103.63) v3(41.68,101.09) v3(42.01,82.7) v3(42.04,80.52) v3(42.09,95.07) v3(42.11,93.55) v3(42.14,91.68) v3(42.14,90.74) v3(42.34,89.97) v3(42.67,108.46) v3(43.08,99.57) v3(43.08,77.93) v3(43.26,100.86) v3(43.26,38) v3(43.31,55.12) v3(43.31,52.58) v3(43.31,50.04) v3(43.31,47.5) v3(43.31,41.15) v3(43.31,36.07) v3(43.31,33.53) v3(43.56,113.03) v3(43.54,65.66) v3(43.66,78.66) v3(43.64,66.47) v3(43.82,99.06) v3(43.82,90.22) v3(43.79,89.71) v3(43.94,67.56) v3(43.94,44.42) v3(44.2,100.34) v3(44.53,66.45) v3(44.81,110.52) v3(44.78,60.23) v3(44.91,65.68) v3(45.03,99.03) v3(45.11,100.89) v3(45.11,99.82) v3(45.46,82.67) v3(45.62,110.1) v3(45.85,80.52) v3(45.85,77.98) v3(45.85,52.58) v3(45.85,50.04) v3(45.85,47.5) v3(45.85,41.15) v3(45.8,38) v3(45.85,36.07) v3(45.85,33.53) v3(45.95,63.27) v3(45.95,61.77) v3(46.1,113.03) v3(46.2,72.09) v3(46.43,67.3) v3(46.48,44.42) v3(46.58,110.64) v3(46.69,109.5) v3(46.69,98.76) v3(46.76,63.27) v3(46.76,61.72) v3(47.12,74.17) v3(47.42,71.83) v3(47.55,109.19) v3(47.55,82.73) v3(47.85,86.98) v3(47.96,67.87) v3(47.98,84.5) v3(48.06,66.85) v3(48.34,38) v3(48.39,100.84) v3(48.39,76.71) v3(48.39,52.58) v3(48.39,50.04) v3(48.39,47.5) v3(48.39,41.15) v3(48.39,36.07) v3(48.39,33.53) v3(48.64,113.03) v3(48.95,67.37) v3(49.66,91.95) v3(49.86,75.49) v3(49.86,66.9) v3(49.83,60.53) v3(49.89,67.92) v3(50.04,89.53) v3(50.04,87) v3(50.19,84.33) v3(50.67,50.47) v3(50.88,38) v3(50.93,111) v3(50.93,108.46) v3(50.93,105.92) v3(50.93,103.38) v3(50.93,100.84) v3(50.93,98.3) v3(50.93,95.76) v3(50.95,55.17) v3(50.9,52.53) v3(50.93,41.15) v3(50.93,36.07) v3(50.93,33.53) v3(51.05,113.03) v3(51.03,66.78) v3(51.56,74.75) v3(51.64,67.97) v3(51.64,67.16) v3(52.2,93.22) v3(52.2,90.68) v3(52.2,88.14) v3(52.76,57.63) v3(52.86,60.5) v3(52.96,113.03) v3(53.47,111) v3(53.47,108.46) v3(53.47,105.92) v3(53.47,103.38) v3(53.47,100.84) v3(53.47,98.3) v3(53.47,95.76) v3(53.44,43.38) v3(53.47,41.15) v3(53.42,38) v3(53.47,36.07) v3(53.47,33.53) v3(54.61,67.82) v3(54.74,93.22) v3(54.74,90.68) v3(54.74,88.14) v3(54.76,86.03) v3(54.86,62.87) v3(55.07,50.47) v3(55.5,113.03) v3(55.63,61.57) v3(55.7,57.58) v3(55.95,38) v3(56.01,111) v3(56.01,108.46) v3(56.01,105.92) v3(56.01,103.38) v3(56.01,100.84) v3(56.01,98.3) v3(56.01,95.76) v3(56.01,65.28) v3(56,36.07) v3(56.01,33.53) v3(56.64,51.44) v3(57.28,93.22) v3(57.28,90.68) v3(57.28,88.14) v3(57.3,86.08) v3(57.63,80.52) v3(57.63,79.2) v3(58.04,113.03) v3(58.32,79.65) v3(58.34,45.11) v3(58.34,38.07) v3(58.55,111) v3(58.55,108.46) v3(58.55,105.92) v3(58.55,103.38) v3(58.55,100.84) v3(58.55,98.3) v3(58.55,95.76) v3(58.55,72.9) v3(58.55,33.53) v3(58.9,79.2) v3(59.59,61.59) v3(59.82,93.22) v3(59.82,90.68) v3(59.82,88.14) v3(59.82,85.6) v3(60.31,65.69) v3(61.09,111) v3(61.09,108.46) v3(61.09,105.92) v3(61.09,103.38) v3(61.09,100.84) v3(61.09,98.3) v3(61.09,95.76) v3(61.09,83.06) v3(61.09,80.52) v3(61.09,77.98) v3(61.09,75.44) v3(61.09,72.9) v3(61.09,70.36) v3(61.09,67.82) v3(61.21,113.03) v3(61.29,45.16) v3(62.36,93.22) v3(62.36,90.68) v3(62.36,88.14) v3(62.36,85.6) v3(63.12,113.03) v3(63.63,111) v3(63.63,108.46) v3(63.63,105.92) v3(63.63,103.38) v3(63.63,100.84) v3(63.63,98.3) v3(63.63,95.76) v3(63.63,83.06) v3(63.63,80.52) v3(63.63,77.98) v3(63.63,75.44) v3(63.63,72.9) v3(63.63,70.36) v3(63.63,67.82) v3(64.9,93.22) v3(64.9,85.6) v3(64.9,33.53) v3(65.1,45.36) v3(65.1,44.3) v3(65.13,40.94) v3(65.13,39.85) v3(65.13,38.28) v3(65.23,36.12) v3(65.66,113.03) v3(65.74,59.59) v3(65.94,45.39) v3(65.94,44.3) v3(65.91,40.94) v3(65.94,39.85) v3(65.99,95.96) v3(66.17,83.06) v3(66.17,80.52) v3(66.17,77.98) v3(66.17,75.44) v3(66.17,72.9) v3(67.44,93.22) v3(67.44,85.6) v3(67.44,33.53) v3(67.51,95.15) v3(67.67,38.28) v3(67.77,36.12) v3(68.71,83.06) v3(68.71,80.52) v3(68.71,77.98) v3(68.71,75.44) v3(68.71,72.9) v3(69.98,95.17) v3(69.98,93.22) v3(69.98,85.6) v3(69.98,33.53) v3(70.26,64.06) v3(70.21,38.28) v3(70.33,62.79) v3(70.31,36.12) v3(70.89,69.24) v3(70.94,67.06) v3(71.25,90.68) v3(71.25,88.14) v3(71.25,83.06) v3(71.25,80.52) v3(71.25,77.98) v3(71.25,75.44) v3(71.25,72.9) v3(72.52,85.6) v3(72.54,67.28) v3(72.49,64.08) v3(72.52,33.53) v3(72.77,62.87) v3(72.77,60.2) v3(72.77,57.53) v3(72.75,38.28) v3(72.85,36.12) v3(72.92,69.16) v3(73.23,66.32) v3(73.25,45.39) v3(73.25,44.25) v3(73.25,40.94) v3(73.25,39.83) v3(73.61,68.61) v3(73.79,90.68) v3(73.79,88.14) v3(73.79,83.06) v3(73.79,80.52) v3(73.79,77.98) v3(73.79,75.44) v3(73.79,72.9) v3(73.91,65.63) v3(74.07,45.39) v3(74.04,44.27) v3(74.07,40.94) v3(74.07,39.83) v3(74.24,48.92) v3(74.57,85.65) v3(74.78,67.87) v3(75.06,33.53) v3(75.28,38.28) v3(75.38,36.12) v3(75.72,90.7) v3(75.72,88.8) v3(75.72,87.07) v3(75.72,66.9) v3(76.15,85.65) v3(76.33,83.06) v3(76.33,80.52) v3(76.33,77.98) v3(76.33,75.44) v3(76.33,72.9) v3(76.33,70.36) v3(76.86,66.9) v3(76.91,64.11) v3(77.32,84.51) v3(77.55,38.25) v3(77.6,67.82) v3(77.6,36.12) v3(77.6,33.53) v3(77.85,90.7) v3(77.85,88.8) v3(77.85,87.07) v3(78.87,83.06) v3(78.87,80.52) v3(78.87,77.98) v3(78.87,75.44) v3(78.87,72.9) v3(78.87,70.36) v3(78.87,66.85) v3(78.89,84.07) v3(78.89,64.16) v3(78.99,86.26) v3(78.99,54.36) v3(79.38,48.9) v3(79.35,47.37) v3(79.63,49.4) v3(80.14,67.82) v3(80.14,33.53) v3(80.26,63.88) v3(80.26,61.21) v3(80.26,56.52) v3(80.26,54.61) v3(80.26,48.13) v3(80.77,49.4) v3(80.85,86.23) v3(80.87,84.1) v3(81.15,48.9) v3(81.15,47.4) v3(81.28,66.93) v3(81.41,90.68) v3(81.41,88.14) v3(81.41,83.06) v3(81.45,68.73) v3(81.46,67.89) v3(81.46,64.11) v3(81.48,44.35) v3(81.48,38.48) v3(81.66,70.97) v3(81.58,69.67) v3(81.69,81.66) v3(81.74,80.29) v3(81.71,78.51) v3(81.71,76.4) v3(81.69,74.4) v3(81.69,72.62) v3(81.81,46.81) v3(82.39,64.08) v3(82.68,33.53) v3(83.03,86.31) v3(83.03,84.07) v3(83.01,47.42) v3(83.03,38) v3(83.11,95.17) v3(83.74,50.32) v3(83.72,49.2) v3(83.72,48.11) v3(83.72,47.09) v3(83.74,44.55) v3(83.72,43.38) v3(83.74,41.73) v3(83.95,93.22) v3(83.95,90.68) v3(83.95,88.14) v3(83.9,40.01) v3(84.02,81.66) v3(84.02,80.39) v3(84.05,78.56) v3(84.02,76.45) v3(84.02,74.4) v3(84.02,72.62) v3(84,70.97) v3(84.1,69.7) v3(84.15,36.68) v3(84.23,68.65) v3(84.24,67.82) v3(84.45,66.93) v3(85.19,86.36) v3(85.22,33.53) v3(85.37,95.15) v3(85.42,82.04) v3(85.47,61.47) v3(85.47,60.45) v3(85.47,59.44) v3(85.47,58.42) v3(85.47,57.4) v3(85.47,56.39) v3(85.47,55.37) v3(85.78,40.01) v3(85.85,49.15) v3(85.93,48.03) v3(85.95,47.04) v3(85.9,44.53) v3(85.95,42.47) v3(86.06,37.03) v3(86.11,50.29) v3(86.2,73.86) v3(86.49,93.22) v3(86.49,90.68) v3(86.49,60.45) v3(86.49,59.44) v3(86.49,58.42) v3(86.49,57.4) v3(86.49,56.39) v3(86.49,55.37) v3(86.66,38.46) v3(86.74,66.93) v3(86.79,87.83) v3(86.87,49.15) v3(86.91,67.94) v3(87.17,95.83) v3(87.08,84.67) v3(87.12,79.83) v3(87.12,78.46) v3(87.12,77.01) v3(87.12,70.74) v3(87.2,81.15) v3(87.35,69.9) v3(87.5,97.92) v3(87.5,60.45) v3(87.5,59.44) v3(87.5,58.42) v3(87.5,57.4) v3(87.5,56.39) v3(87.5,55.37) v3(87.76,33.53) v3(87.81,75.41) v3(87.86,72.42) v3(88.21,89.26) v3(88.49,86.33) v3(88.52,61.47) v3(88.52,60.45) v3(88.52,59.44) v3(88.52,58.42) v3(88.52,57.4) v3(88.52,56.39) v3(88.52,55.37) v3(88.85,49.3) v3(89.03,93.22) v3(89.26,69.93) v3(89.25,38.46) v3(89.46,81.03) v3(89.46,79.83) v3(89.46,78.46) v3(89.46,77.01) v3(89.38,74.75) v3(89.46,70.74) v3(89.48,73.05) v3(89.53,61.47) v3(89.53,60.45) v3(89.53,59.44) v3(89.53,58.42) v3(89.53,57.4) v3(89.53,56.39) v3(89.53,55.37) v3(89.61,90.65) v3(89.61,86.39) v3(89.76,87.55) v3(89.77,67.98) v3(89.87,45.19) v3(89.79,44.25) v3(89.92,66.93) v3(90.02,65.38) v3(90.09,35.88) v3(90.3,108.46) v3(90.3,105.92) v3(90.3,95.76) v3(90.3,33.53) v3(90.55,61.47) v3(90.55,60.45) v3(90.55,59.44) v3(90.55,58.42) v3(90.55,57.4) v3(90.55,56.39) v3(90.55,55.37) v3(90.55,42.11) v3(90.73,67.67) v3(90.96,91.97) v3(91.06,100.23) v3(90.98,87.73) v3(91.08,88.85) v3(91.26,104.44) v3(91.26,82.73) v3(91.21,74.75) v3(91.26,38.45) v3(91.29,77.01) v3(91.29,73.05) v3(91.29,70.74) v3(91.36,69.07) v3(91.4,84.67) v3(91.54,102.59) v3(91.57,61.47) v3(91.57,60.45) v3(91.57,59.44) v3(91.57,58.42) v3(91.57,57.4) v3(91.57,56.39) v3(91.57,55.37) v3(91.82,79.07) v3(92.07,65.91) v3(92.05,41.45) v3(92.13,49.3) v3(92.15,45.24) v3(92.2,112.75) v3(92.2,111.46) v3(92.2,110.26) v3(92.2,105.66) v3(92.25,97.46) v3(92.2,93.29) v3(92.25,89.05) v3(92.28,108.51) v3(92.28,99.14) v3(92.41,90.2) v3(92.46,68.38) v3(92.57,35.93) v3(92.71,81.13) v3(92.84,95.76) v3(92.81,86.16) v3(92.84,33.53) v3(92.89,107.26) v3(92.94,44.27) v3(92.97,40.86) v3(93.24,77.04) v3(93.27,73.05) v3(93.2,63.08) v3(93.37,106.05) v3(93.37,103.78) v3(93.29,74.78) v3(93.34,70.71) v3(93.47,94.54) v3(93.46,65.93) v3(93.42,49.3) v3(93.5,96.16) v3(93.57,90.35) v3(93.73,91.49) v3(93.73,87.22) v3(93.78,68.66) v3(93.8,38.45) v3(93.95,100.94) v3(93.95,44.29) v3(94.01,81.15) v3(93.98,50.29) v3(94.01,40.93) v3(94.08,86.16) v3(94.11,60.51) v3(94.36,108.86) v3(94.28,106.68) v3(94.34,102.92) v3(94.31,95.43) v3(94.41,112.78) v3(94.41,111.48) v3(94.39,110.24) v3(94.56,69.6) v3(94.84,106.07) v3(94.87,103.86) v3(94.82,91.62) v3(94.82,83.66) v3(94.86,65.71) v3(94.84,63.7) v3(94.87,58.7) v3(94.89,76.4) v3(95.07,92.86) v3(95.07,71.48) v3(95.12,88.7) v3(95.12,68.38) v3(95.11,44.34) v3(95.11,40.86) v3(95.11,35.93) v3(95.28,95.96) v3(95.25,86.26) v3(95.38,81.05) v3(95.38,33.53) v3(95.43,54.28) v3(95.5,108.86) v3(95.53,106.71) v3(95.63,74.78) v3(95.61,73.05) v3(95.88,93.78) v3(96.01,101.17) v3(96,61.24) v3(96.11,106.07) v3(96.14,48.13) v3(96.16,44.35) v3(96.27,103.89) v3(96.19,60.2) v3(96.27,58.15) v3(96.27,49.28) v3(96.37,93.19) v3(96.37,70.43) v3(96.37,68.66) v3(96.34,38.45) v3(96.39,89.92) v3(96.44,86.31) v3(96.52,81.05) v3(96.9,48.77) v3(97.03,97.82) v3(97.05,79.93) v3(97.08,108.59) v3(97.16,44.32) v3(97.26,40.82) v3(97.28,99.97) v3(97.54,80.87) v3(97.61,86.41) v3(97.64,58.57) v3(97.66,54.74) v3(97.66,49.4) v3(97.66,48.13) v3(97.71,104.6) v3(97.84,68.4) v3(97.92,103.38) v3(97.92,100.84) v3(97.92,75.44) v3(97.92,71.63) v3(97.92,33.53) v3(98.02,91.54) v3(98.12,107.57) v3(98.23,62.03) v3(98.19,59.97) v3(98.25,40.89) v3(98.32,106.02) v3(98.35,44.32) v3(98.57,94.85) v3(98.65,86.54) v3(98.68,80.77) v3(98.75,58.62) v3(99.01,98.18) v3(99.03,68.71) v3(99.08,63.07) v3(99.11,54.25) v3(99.11,49.96) v3(99.11,47.42) v3(99.19,88.14) v3(99.24,65.33) v3(99.36,90.02) v3(99.29,44.35) v3(99.29,40.89) v3(99.7,61.63) v3(99.82,50.8) v3(100.01,37.42) v3(100.1,97.08) v3(100.27,64.76) v3(100.33,68.81) v3(100.29,60.2) v3(100.31,58.16) v3(100.38,113.03) v3(100.38,111.02) v3(100.46,108.46) v3(100.46,105.92) v3(100.46,103.38) v3(100.46,100.84) v3(100.46,98.3) v3(100.46,33.53) v3(100.53,84.71) v3(100.51,82.63) v3(100.66,54.31) v3(100.96,50.8) v3(101.07,60.71) v3(101.07,57.63) v3(101.21,61.69) v3(101.3,63.74) v3(101.38,97.12) v3(101.47,81.25) v3(101.55,66.21) v3(101.55,65.06) v3(101.58,68.52) v3(101.65,49.96) v3(101.65,47.42) v3(101.73,86.87) v3(101.82,37.05) v3(102.06,90.02) v3(102.11,60.6) v3(102.17,57.78) v3(102.23,44.95) v3(102.23,40.28) v3(102.34,84.71) v3(102.31,82.63) v3(102.64,61.37) v3(102.77,97.05) v3(102.77,68.53) v3(102.83,113.03) v3(102.79,94.77) v3(102.79,64.21) v3(102.92,111.02) v3(103,108.46) v3(103,105.92) v3(103,103.38) v3(103,100.84) v3(103,98.3) v3(103,66.22) v3(103.23,81.28) v3(103.25,72.29) v3(103.32,33.56) v3(103.43,91.44) v3(103.43,88.67) v3(103.45,37.02) v3(103.48,94.03) v3(103.78,61.29) v3(103.89,64.21) v3(103.94,60.25) v3(104.06,84.73) v3(104.04,82.65) v3(104.01,57.99) v3(104.01,56.64) v3(104.17,68.53) v3(104.24,49.99) v3(104.24,47.45) v3(104.37,97.05) v3(104.44,94.77) v3(104.44,53.95) v3(104.52,65.48) v3(104.67,90.22) v3(104.72,87.3) v3(104.88,8.92) v3(104.88,6.38) v3(104.88,3.84) v3(104.92,34.63) v3(104.93,32.59) v3(104.93,30.05) v3(104.95,27.41) v3(104.95,24.87) v3(104.93,22.58) v3(104.93,20.04) v3(104.9,13.74) v3(104.9,11.2) v3(105.05,37.08) v3(104.98,0.79) v3(105.21,113) v3(105.46,111.02) v3(105.46,60.25) v3(105.54,108.46) v3(105.54,105.92) v3(105.54,103.38) v3(105.54,100.84) v3(105.54,98.3) v3(105.56,86.49) v3(105.49,63.91) v3(105.49,61.52) v3(105.51,57.94) v3(105.64,91.82) v3(105.71,94.13) v3(105.79,77.06) v3(105.94,88.95) v3(106.17,73.94) v3(106.17,72.34) v3(106.15,70.59) v3(106.22,75.18) v3(106.25,37.08) v3(106.32,97.05) v3(106.32,94.77) v3(106.38,54.99) v3(106.45,60.53) v3(106.4,56.82) v3(106.73,91.29) v3(106.68,8.31) v3(106.81,65.84) v3(106.78,49.99) v3(106.78,47.45) v3(106.86,12.47) v3(106.96,67.11) v3(107.09,52.65) v3(107.24,59.69) v3(107.19,20.12) v3(107.37,23.39) v3(107.44,37.08) v3(107.42,26.62) v3(107.52,94.06) v3(107.49,56.16) v3(107.54,34.32) v3(107.56,29.18) v3(107.52,0.79) v3(107.6,31.89) v3(107.76,91.3) v3(107.72,89.95) v3(107.7,88.95) v3(108.08,108.46) v3(108.08,105.92) v3(108.08,103.38) v3(108.08,100.84) v3(108.08,98.3) v3(108.08,62.46) v3(108.33,97.05) v3(108.33,94.74) v3(108.31,73.91) v3(108.33,72.39) v3(108.33,70.64) v3(108.28,65.76) v3(108.28,58.55) v3(108.51,61.52) v3(108.61,68.68) v3(108.71,103.12) v3(108.71,101.88) v3(108.69,36.63) v3(108.86,54.81) v3(108.97,104.42) v3(109.05,53.18) v3(109.22,93.7) v3(109.22,8.31) v3(109.32,49.99) v3(109.32,47.45) v3(109.4,12.47) v3(109.61,51.74) v3(109.73,97.03) v3(109.73,20.12) v3(109.78,91.34) v3(109.93,92.65) v3(109.93,89.89) v3(109.96,26.62) v3(109.91,23.39) v3(109.99,89.1) v3(110.06,0.79) v3(110.08,34.32) v3(110.14,31.89) v3(110.1,29.18) v3(110.26,93.53) v3(110.21,64.01) v3(110.36,90.67) v3(110.54,56.46) v3(110.74,112.78) v3(110.72,111.25) v3(110.72,109.8) v3(110.74,108.2) v3(110.71,106.64) v3(110.74,105.34) v3(110.77,99.31) v3(110.77,96.16) v3(110.73,89.88) v3(110.72,59.41) v3(110.79,100.74) v3(110.79,97.79) v3(110.8,92.28) v3(110.85,62.92) v3(110.78,15.49) v3(110.93,91.35) v3(111.04,53.09) v3(111,51.07) v3(111.12,66.14) v3(111.18,44.5) v3(111.18,43.28) v3(111.53,36.63) v3(111.66,61.49) v3(111.71,68.71) v3(111.76,8.31) v3(111.84,71.65) v3(111.86,49.99) v3(111.86,47.45) v3(111.94,12.47) v3(112.01,65.25) v3(112.14,54.84) v3(112.27,20.12) v3(112.29,58.29) v3(112.34,44.5) v3(112.34,43.28) v3(112.45,23.39) v3(112.5,26.62) v3(112.62,51.07) v3(112.62,34.32) v3(112.64,29.18) v3(112.6,0.79) v3(112.75,61.44) v3(112.68,31.89) v3(112.84,3.21) v3(112.95,67.54) v3(112.9,5.94) v3(113.04,112.77) v3(113.05,111.22) v3(113.05,109.77) v3(113.03,108.15) v3(113.04,106.6) v3(113.04,105.39) v3(113.06,100.76) v3(113.03,99.31) v3(113.06,97.79) v3(113.03,96.16) v3(113.03,94.64) v3(113.07,93.53) v3(113.07,92.49) v3(113.04,91.36) v3(113.06,64.24) v3(113.38,90.14) v3(113.61,63.68) v3(113.59,56.59) v3(113.64,53.34) v3(113.61,44.48) v3(113.61,43.26) v3(113.77,49.91) v3(113.79,69.62) v3(114.12,60.07) v3(114.43,108.46) v3(114.43,105.92) v3(114.48,47.45) v3(114.51,36.68) v3(114.48,23.45) v3(114.73,104.47) v3(114.82,48.85) v3(114.78,44.48) v3(114.78,43.26) v3(114.96,87.83) v3(114.96,51.99) v3(115.06,103.12) v3(115.06,101.85) v3(114.99,90.12) v3(115.16,68.22) v3(115.16,34.32) v3(115.14,0.79) v3(115.19,65.28) v3(115.22,31.89) v3(115.18,29.18) v3(115.36,26.68) v3(115.38,3.21) v3(115.44,92.54) v3(115.47,55.42) v3(115.44,5.94) v3(115.67,61.65) v3(115.65,58.5) v3(115.6,22.91) v3(115.6,21.18) v3(115.7,100.84) v3(115.7,98.3) v3(115.7,95.76) v3(115.7,70.59) v3(115.87,44.48) v3(115.87,43.26) v3(116,74.7) v3(116.43,24.71) v3(116.48,90.09) v3(116.51,53.52) v3(116.56,50.37) v3(116.64,66.75) v3(116.71,46.91) v3(116.86,45) v3(116.83,26.12) v3(116.97,108.46) v3(116.97,105.92) v3(116.97,103.38) v3(117.17,60.15) v3(117.27,63.14) v3(117.27,56.82) v3(117.45,90.07) v3(117.46,43.2) v3(117.63,27.18) v3(117.68,36.73) v3(117.7,34.32) v3(117.76,31.89) v3(117.72,29.18) v3(117.68,0.79) v3(117.86,22.91) v3(117.86,21.13) v3(117.94,92.5) v3(117.92,3.21) v3(118.01,86.51) v3(118.03,74.75) v3(117.98,5.94) v3(118.14,72.47) v3(118.14,68.15) v3(118.14,48.84) v3(118.24,100.84) v3(118.24,98.3) v3(118.24,95.76) v3(118.19,89.38) v3(118.19,71.09) v3(118.39,110.77) v3(118.41,52.12) v3(118.57,112.93) v3(118.59,55.5) v3(118.74,64.67) v3(118.74,58.6) v3(118.71,39.77) v3(118.87,61.54) v3(118.95,24) v3(119.08,44.8) v3(119.08,25.45) v3(119.12,42.5) v3(119.2,27.92) v3(119.43,90.7) v3(119.41,78.05) v3(119.51,108.46) v3(119.51,105.92) v3(119.51,103.38) v3(119.52,21.87) v3(119.63,87.99) v3(119.66,84.71) v3(119.66,82.63) v3(119.63,71.64) v3(119.58,69.65) v3(119.71,50.34) v3(120.15,94.12) v3(120.17,57.15) v3(120.17,46.84) v3(120.22,91.44) v3(120.19,66.14) v3(120.29,63.09) v3(120.29,60.15) v3(120.35,53.75) v3(120.35,28.68) v3(120.42,87.11) v3(120.4,0.79) v3(120.63,3.21) v3(120.75,25.83) v3(120.7,5.94) v3(120.78,100.84) v3(120.78,98.3) v3(120.8,89.18) v3(120.86,81.01) v3(120.93,110.77) v3(120.89,22.92) v3(121.02,95) v3(121.07,70.94) v3(121.04,68.3) v3(121.11,112.93) v3(121.16,78.82) v3(121.16,40.44) v3(121.16,38.66) v3(121.26,86.26) v3(121.18,42.49) v3(121.18,41.43) v3(121.18,36.73) v3(121.18,35.33) v3(121.21,33.93) v3(121.18,32.49) v3(121.18,31.12) v3(121.21,29.51) v3(121.31,51.92) v3(121.31,24.54) v3(121.41,45.54) v3(121.65,90.04) v3(121.69,64.62) v3(121.77,58.7) v3(121.72,26.82) v3(121.79,61.65) v3(121.97,82.63) v3(121.93,75.09) v3(121.97,48.39) v3(121.95,21.91) v3(122.05,108.46) v3(122.05,105.92) v3(122.05,103.38) v3(122.07,95.66) v3(122.08,85.46) v3(122.1,55.22) v3(122.24,51.82) v3(122.54,87.81) v3(122.77,70.96) v3(122.73,66.57) v3(122.73,27.79) v3(122.86,84.71) v3(122.83,81.58) v3(122.81,68.3) v3(122.94,96.52) v3(122.94,0.79) v3(122.99,44.04) v3(123.13,80.81) v3(123.14,47.14) v3(123.17,3.21) v3(123.2,79.06) v3(123.27,62.89) v3(123.22,60.25) v3(123.27,57.15) v3(123.22,54.03) v3(123.22,50.62) v3(123.19,26.52) v3(123.22,24.77) v3(123.19,23.32) v3(123.19,21.06) v3(123.24,5.94) v3(123.32,100.84) v3(123.32,98.3) v3(123.34,40.39) v3(123.34,38.61) v3(123.34,36.7) v3(123.34,35.33) v3(123.37,33.93) v3(123.34,32.49) v3(123.34,31.12) v3(123.37,29.51) v3(123.47,110.77) v3(123.65,112.93) v3(123.65,97.28) v3(123.98,65.33) v3(124.17,90.03) v3(124.54,98.2) v3(124.49,74.82) v3(124.56,71.05) v3(124.59,108.46) v3(124.59,105.92) v3(124.59,103.38) v3(124.59,76.71) v3(124.59,72.9) v3(124.74,77.93) v3(124.83,68.3) v3(124.95,90.82) v3(125.1,94.95) v3(125.12,86.53) v3(125.12,80.81) v3(125.15,66.52) v3(125.22,64.06) v3(125.45,60.91) v3(125.45,58.06) v3(125.45,55.02) v3(125.48,51.87) v3(125.48,48.51) v3(125.48,35.31) v3(125.48,32.49) v3(125.48,31.12) v3(125.48,23.32) v3(125.48,0.79) v3(125.5,44.88) v3(125.5,41.63) v3(125.5,38.18) v3(125.5,36.65) v3(125.5,33.93) v3(125.5,29.51) v3(125.5,27.08) v3(125.5,25.32) v3(125.5,21.06) v3(125.7,91.92) v3(125.71,3.21) v3(125.78,5.94) v3(125.88,76.74) v3(126.34,100.05) v3(126.42,86.23) v3(126.49,97.97) v3(126.54,92.76) v3(126.49,81.08) v3(126.88,79.09) v3(126.94,75.74) v3(126.97,71.36) v3(126.97,59.21) v3(126.97,46.76) v3(126.95,43.35) v3(126.97,35.33) v3(126.97,32.49) v3(126.97,31.12) v3(126.97,27.66) v3(126.97,23.39) v3(126.97,21.01) v3(127.03,74.52) v3(127,72.97) v3(127,69.82) v3(127,68.33) v3(127,66.57) v3(127,65.33) v3(127,63.83) v3(127.03,62.26) v3(127.03,56.39) v3(127.03,53.39) v3(127.03,50.22) v3(127,40.03) v3(127.03,36.6) v3(127,33.93) v3(127,29.51) v3(127.03,25.5) v3(127.33,93.5) v3(127.38,103.4) v3(127.56,86.28) v3(127.53,81.05) v3(127.58,101.3) v3(127.67,78.29) v3(127.79,105.84) v3(127.99,107.44) v3(128.02,96.55) v3(128.02,0.79) v3(128.25,3.21) v3(128.32,5.94) v3(128.4,104.52) v3(128.4,94.51) v3(128.4,93.22) v3(128.4,90.68) v3(128.4,88.14) v3(128.55,77.34) v3(128.6,81.03) v3(128.7,86.26) v3(128.96,83.66) v3(129.06,108.76) v3(129.16,41.22) v3(129.26,75.97) v3(129.26,74.52) v3(129.24,72.97) v3(129.26,71.4) v3(129.24,69.82) v3(129.24,68.33) v3(129.24,66.57) v3(129.24,65.33) v3(129.24,63.83) v3(129.26,62.26) v3(129.24,60.02) v3(129.26,54.28) v3(129.26,51.16) v3(129.26,48.03) v3(129.26,37.9) v3(129.26,35.69) v3(129.26,32.49) v3(129.26,29.44) v3(129.26,27.66) v3(129.26,25.4) v3(129.24,23.34) v3(129.26,21.08) v3(129.36,111.2) v3(129.36,109.88) v3(129.29,57.1) v3(129.29,44.65) v3(129.29,36.5) v3(129.28,34.4) v3(129.29,31.06) v3(129.39,112.62) v3(129.77,103.63) v3(129.69,101.09) v3(129.87,86.31) v3(129.9,81) v3(130.07,96.22) v3(130.07,26.09) v3(130.18,105.82) v3(130.25,106.83) v3(130.33,40.11) v3(130.42,102.49) v3(130.56,0.79) v3(130.66,31.88) v3(130.69,58.58) v3(130.69,30.81) v3(130.82,55.43) v3(130.78,34.19) v3(130.86,5.94) v3(130.79,3.21) v3(130.94,95.76) v3(130.94,93.22) v3(130.94,90.68) v3(130.94,88.14) v3(130.94,79.25) v3(130.94,76.71) v3(130.94,74.17) v3(130.94,71.63) v3(130.96,52.43) v3(130.99,49.45) v3(131.05,46.28) v3(131.04,42.9) v3(131.06,22.96) v3(131.11,108.03) v3(131.14,99.62) v3(131.17,86.36) v3(131.14,81.03) v3(131.08,68.3) v3(131.11,36.02) v3(131.17,21.52) v3(131.27,103.61) v3(131.32,105.77) v3(131.32,97.49) v3(131.57,112.65) v3(131.55,111.23) v3(131.52,109.88) v3(131.67,38.73) v3(131.83,31.83) v3(132.21,65.28) v3(132.21,62.74) v3(132.21,60.2) v3(132.21,41.78) v3(132.41,29.79) v3(132.56,103.56) v3(132.49,56.81) v3(132.55,53.7) v3(132.61,26.09) v3(132.72,102.03) v3(132.73,50.72) v3(132.75,47.73) v3(132.87,44.48) v3(132.89,34.16) v3(133.07,105.71) v3(133.17,107.92) v3(133.12,37.29) v3(133.1,0.79) v3(133.22,103.02) v3(133.3,99.42) v3(133.33,3.21) v3(133.48,98.3) v3(133.48,95.76) v3(133.48,93.22) v3(133.48,90.68) v3(133.48,88.14) v3(133.45,86.36) v3(133.45,81) v3(133.48,79.25) v3(133.48,76.71) v3(133.48,74.17) v3(133.48,71.63) v3(133.4,5.94) v3(133.55,40.41) v3(133.52,28.01) v3(133.62,68.3) v3(133.6,22.96) v3(134.04,43.36) v3(134.08,55.22) v3(134.12,32.81) v3(134.11,31.27) v3(134.19,100.43) v3(134.26,51.95) v3(134.2,24.63) v3(134.37,49.03) v3(134.44,105.03) v3(134.54,45.9) v3(134.59,35.76) v3(134.75,65.28) v3(134.75,62.74) v3(134.75,60.2) v3(134.75,57.66) v3(134.77,28.91) v3(135,38.96) v3(135.23,101.63) v3(135.2,86.33) v3(135.18,81.03) v3(135.21,31.76) v3(135.28,103.68) v3(135.38,41.99) v3(135.46,26.8) v3(135.64,0.79) v3(135.71,44.78) v3(135.85,53.47) v3(135.87,3.21) v3(135.94,50.29) v3(135.97,34.39) v3(135.88,25.59) v3(135.94,5.94) v3(136.02,108.46) v3(136.02,105.92) v3(136.02,103.38) v3(136.02,100.84) v3(136.02,98.3) v3(136.02,95.76) v3(136.02,93.22) v3(136.02,90.68) v3(136.02,88.14) v3(136.02,79.25) v3(136.02,76.71) v3(136.02,74.17) v3(136.02,71.63) v3(136.16,68.3) v3(136.17,47.27) v3(136.14,22.96) v3(136.47,37.44) v3(136.42,30.51) v3(136.68,82.6) v3(136.83,40.54) v3(136.97,24.53) v3(137.06,43.41) v3(137.06,28.35) v3(137.29,65.28) v3(137.29,62.74) v3(137.29,60.2) v3(137.29,57.66) v3(137.29,55.12) v3(137.34,46.15) v3(137.44,32.97) v3(137.53,51.73) v3(137.62,48.64) v3(137.62,29.36) v3(137.69,26.09) v3(137.85,36.07) v3(138.18,0.79) v3(138.2,81.03) v3(138.3,39.01) v3(138.41,3.21) v3(138.56,93.22) v3(138.56,90.68) v3(138.56,88.14) v3(138.56,79.25) v3(138.56,76.71) v3(138.56,74.17) v3(138.56,71.63) v3(138.51,41.96) v3(138.48,5.94) v3(138.7,68.3) v3(138.68,44.78) v3(138.68,22.96) v3(138.86,95.12) v3(138.79,47.52) v3(138.79,28.12) v3(138.91,31.47) v3(139.19,50.06) v3(139.32,34.65) v3(139.57,83.24) v3(139.5,24.96) v3(139.6,81.05) v3(139.67,37.64) v3(139.75,26.93) v3(139.83,65.28) v3(139.83,62.74) v3(139.83,60.2) v3(139.83,57.66) v3(139.83,55.12) v3(139.83,52.58) v3(139.95,21.61) v3(139.98,40.44) v3(140.13,46.15) v3(140.13,43.33) v3(140.36,48.95) v3(140.49,29.9) v3(140.52,26.84) v3(140.53,24.94) v3(140.72,0.79) v3(140.79,33.15) v3(140.89,83.9) v3(140.97,81.36) v3(140.95,3.21) v3(141.02,95.12) v3(141.02,5.94) v3(141.1,93.22) v3(141.1,90.68) v3(141.1,88.14) v3(141.1,85.6) v3(141.1,79.25) v3(141.1,76.71) v3(141.1,74.17) v3(141.1,71.63) v3(141.15,36.22) v3(141.24,68.3) v3(141.21,28.74) v3(141.22,22.96) v3(141.35,39.07) v3(141.28,26.73) v3(141.58,44.7) v3(141.61,41.81) v3(141.71,47.57) v3(141.9,24.74) v3(142.07,28.76) v3(142.16,85.17) v3(142.14,26.72) v3(142.19,82.14) v3(142.37,65.28) v3(142.37,62.74) v3(142.37,60.2) v3(142.37,57.66) v3(142.37,55.12) v3(142.37,52.58) v3(142.37,50.04) v3(142.37,31.57) v3(142.51,23.53) v3(142.62,34.72) v3(142.82,37.64) v3(142.98,40.44) v3(142.97,21.57) v3(143.05,43.18) v3(143.15,46.13) v3(143.26,0.79) v3(143.46,83.41) v3(143.48,86.41) v3(143.56,5.94) v3(143.49,3.21) v3(143.64,90.68) v3(143.64,88.14) v3(143.64,79.25) v3(143.64,76.71) v3(143.64,74.17) v3(143.64,71.63) v3(143.59,30.33) v3(143.78,68.3) v3(143.82,23.2) v3(143.94,25.09) v3(144.2,33.15) v3(144.3,36.14) v3(144.35,28.93) v3(144.42,41.81) v3(144.45,39.01) v3(144.39,26.84) v3(144.63,44.6) v3(144.73,23.03) v3(144.78,87.73) v3(144.78,84.66) v3(144.86,25.1) v3(144.91,65.28) v3(144.91,62.74) v3(144.91,60.2) v3(144.91,57.66) v3(144.91,55.12) v3(144.91,52.58) v3(144.91,50.04) v3(144.91,47.5) v3(145.42,31.9) v3(145.67,88.93) v3(145.87,95) v3(145.87,93.14) v3(145.87,34.57) v3(145.79,21.62) v3(145.8,0.79) v3(145.9,91.67) v3(145.9,90.17) v3(145.9,40.39) v3(145.92,37.52) v3(146.08,85.98) v3(146,43.23) v3(146.03,3.21) v3(146.1,5.94) v3(146.18,84.33) v3(146.18,81.79) v3(146.18,79.25) v3(146.18,76.71) v3(146.18,74.17) v3(146.18,71.63) v3(146.32,68.3) v3(146.63,30.66) v3(146.84,28.91) v3(146.86,26.8) v3(146.86,25) v3(146.91,23.14) v3(147.09,33.32) v3(147.37,38.89) v3(147.35,20.99) v3(147.45,65.28) v3(147.45,62.74) v3(147.45,60.2) v3(147.45,57.66) v3(147.45,55.12) v3(147.45,52.58) v3(147.45,50.04) v3(147.45,47.5) v3(147.45,44.96) v3(147.47,41.81) v3(147.57,87.86) v3(147.5,35.94) v3(147.57,22.91) v3(147.94,26.8) v3(147.94,25) v3(148.03,95) v3(148.03,93.14) v3(148.06,91.67) v3(148.06,90.17) v3(147.98,28.88) v3(148.34,0.79) v3(148.39,32.05) v3(148.57,3.21) v3(148.64,5.94) v3(148.72,89.41) v3(148.72,86.87) v3(148.72,84.33) v3(148.72,81.79) v3(148.72,79.25) v3(148.72,76.71) v3(148.72,74.17) v3(148.72,71.63) v3(148.72,34.7) v3(148.86,68.3) v3(148.95,40.31) v3(148.95,37.31) v3(149.86,30.58) v3(149.99,65.28) v3(149.99,62.74) v3(149.99,60.2) v3(149.99,57.66) v3(149.99,55.12) v3(149.99,52.58) v3(149.99,50.04) v3(149.99,47.5) v3(149.99,44.96) v3(149.99,42.42) v3(150.04,33.43) v3(150.16,36.07) v3(150.26,22.15) v3(150.34,28.93) v3(150.38,26.87) v3(150.52,38.73) v3(150.49,24.93) v3(150.88,0.79) v3(151.11,3.21) v3(151.26,89.41) v3(151.26,86.87) v3(151.26,84.33) v3(151.26,81.79) v3(151.26,79.25) v3(151.26,76.71) v3(151.26,74.17) v3(151.26,71.63) v3(151.18,5.94) v3(151.36,32.03) v3(151.4,68.3) v3(151.51,34.77) v3(151.74,37.49) v3(152.37,31.09) v3(152.53,65.28) v3(152.53,62.74) v3(152.53,60.2) v3(152.53,57.66) v3(152.53,55.12) v3(152.53,52.58) v3(152.53,50.04) v3(152.53,47.5) v3(152.53,44.96) v3(152.53,42.42) v3(152.53,39.88) v3(152.77,26.56) v3(152.81,33.45) v3(152.96,36.32) v3(152.93,28.93) v3(152.93,23.37) v3(153.16,30.15) v3(153.22,21.54) v3(153.42,0.79) v3(153.65,3.21) v3(153.71,95.11) v3(153.72,5.94) v3(153.8,91.95) v3(153.8,89.41) v3(153.8,86.87) v3(153.8,84.33) v3(153.8,81.79) v3(153.8,79.25) v3(153.8,76.71) v3(153.8,74.17) v3(153.8,71.63) v3(153.94,68.3) v3(154.18,32.11) v3(154.38,34.93) v3(155.07,65.28) v3(155.07,62.74) v3(155.07,60.2) v3(155.07,57.66) v3(155.07,55.12) v3(155.07,52.58) v3(155.07,50.04) v3(155.07,47.5) v3(155.07,44.96) v3(155.07,42.42) v3(155.07,39.88) v3(155.07,37.34) v3(155.13,21.3) v3(155.45,28.91) v3(155.47,26.99) v3(155.58,30.53) v3(155.5,23.88) v3(155.65,33.66) v3(155.96,0.79) v3(156.25,95.11) v3(156.26,5.94) v3(156.19,3.21) v3(156.34,91.95) v3(156.34,89.41) v3(156.34,86.87) v3(156.34,84.33) v3(156.34,81.79) v3(156.34,79.25) v3(156.34,76.71) v3(156.34,74.17) v3(156.34,71.63) v3(156.48,68.3) v3(156.87,32.41) v3(157.55,21.77) v3(157.61,65.28) v3(157.61,62.74) v3(157.61,60.2) v3(157.61,57.66) v3(157.61,55.12) v3(157.61,52.58) v3(157.61,50.04) v3(157.61,47.5) v3(157.61,44.96) v3(157.61,42.42) v3(157.61,39.88) v3(157.61,37.34) v3(157.76,112.89) v3(157.73,109.88) v3(157.73,107.34) v3(157.73,104.8) v3(157.73,102.26) v3(157.73,99.72) v3(157.73,97.18) v3(157.81,34.62) v3(157.84,30.53) v3(157.84,28.88) v3(157.87,24.65) v3(157.88,26.85) v3(158.5,0.79) v3(158.73,3.21) v3(158.83,76.68) v3(158.83,74.07) v3(158.8,5.94) v3(158.88,94.49) v3(158.88,91.95) v3(158.88,89.41) v3(158.88,86.87) v3(158.88,84.33) v3(158.88,81.79) v3(158.88,79.25) v3(158.9,71.6) v3(159.03,68.33) v3(159.33,32.11) v3(159.29,23.15) v3(159.66,27.15) v3(159.66,24.61) v3(159.76,21.13) v3(160.15,65.28) v3(160.15,62.74) v3(160.15,60.2) v3(160.15,57.66) v3(160.15,55.12) v3(160.15,52.58) v3(160.15,50.04) v3(160.15,47.5) v3(160.15,44.96) v3(160.15,42.42) v3(160.15,39.88) v3(160.15,37.34) v3(160.15,29.72) v3(160.27,109.88) v3(160.27,107.34) v3(160.27,104.8) v3(160.27,102.26) v3(160.27,99.72) v3(160.27,97.18) v3(160.3,112.89) v3(160.35,34.62) v3(161.04,0.79) v3(161.27,3.21) v3(161.34,5.94) v3(161.42,94.49) v3(161.42,91.95) v3(161.42,89.41) v3(161.42,86.87) v3(161.42,84.33) v3(161.42,81.79) v3(161.44,77.39) v3(161.5,22.46) v3(161.75,71.53) v3(161.72,69.32) v3(161.87,32.11) v3(162.03,29.72) v3(162.2,27.15) v3(162.2,24.61) v3(162.69,62.74) v3(162.69,60.2) v3(162.69,57.66) v3(162.69,55.12) v3(162.69,52.58) v3(162.69,50.04) v3(162.69,47.5) v3(162.69,44.96) v3(162.69,42.42) v3(162.69,39.88) v3(162.69,37.34) v3(162.84,112.89) v3(162.81,109.88) v3(162.81,107.34) v3(162.81,104.8) v3(162.81,102.26) v3(162.81,99.72) v3(162.81,97.18) v3(162.89,34.62) v3(163.58,0.79) v3(163.86,22.64) v3(163.81,3.21) v3(163.96,94.49) v3(163.96,91.95) v3(163.96,89.41) v3(163.96,86.87) v3(163.96,84.33) v3(163.96,81.79) v3(163.96,29.72) v3(163.88,5.94) v3(164.16,77.39) v3(164.41,32.11) v3(164.67,69.34) v3(164.69,71.63) v3(164.74,27.15) v3(165.21,112.89) v3(165.23,62.74) v3(165.23,60.2) v3(165.23,57.66) v3(165.23,55.12) v3(165.23,52.58) v3(165.23,50.04) v3(165.23,47.5) v3(165.23,44.96) v3(165.23,42.42) v3(165.23,39.88) v3(165.23,37.34) v3(165.35,109.85) v3(165.38,10.08) v3(165.41,107.4) v3(165.43,34.62) v3(165.43,19.91) v3(165.38,7.92) v3(165.5,16.74) v3(165.51,12.17) v3(165.75,24.47) v3(165.79,3.22) v3(165.91,104.77) v3(165.91,102.23) v3(165.91,99.69) v3(165.91,97.15) v3(166.12,0.79) v3(166.29,5.93) v3(166.5,94.49) v3(166.5,91.95) v3(166.5,89.41) v3(166.5,86.87) v3(166.5,84.33) v3(166.5,81.79) v3(166.5,29.72) v3(166.67,77.39) v3(166.59,32.11) v3(166.63,22.11) v3(167.46,71.6) v3(167.46,69.22) v3(167.75,112.89) v3(167.69,67.92) v3(167.77,62.74) v3(167.77,60.2) v3(167.77,57.66) v3(167.77,47.5) v3(167.77,44.96) v3(167.77,42.42) v3(167.77,39.88) v3(167.77,37.34) v3(167.77,25.83) v3(167.84,35.61) v3(167.95,27.07) v3(167.97,19.91) v3(167.91,10.17) v3(167.92,7.92) v3(168.05,12.17) v3(168.45,104.77) v3(168.45,102.23) v3(168.45,99.69) v3(168.45,97.15) v3(168.88,36.32) v3(169.04,94.49) v3(169.04,91.95) v3(169.04,89.41) v3(169.04,86.87) v3(169.04,84.33) v3(169.04,81.79) v3(169.04,79.25) v3(169.04,75.44) v3(169.04,72.9) v3(169.04,22.1) v3(169.01,0.74) v3(169.55,69.57) v3(169.57,67.05) v3(169.49,65.25) v3(169.54,26.52) v3(169.54,24.01) v3(169.65,34.16) v3(169.65,31.62) v3(169.65,29.08) v3(170.29,112.89) v3(170.31,62.74) v3(170.31,60.2) v3(170.31,57.66) v3(170.31,47.5) v3(170.31,44.96) v3(170.31,42.42) v3(170.31,39.88) v3(170.31,37.34) v3(170.46,7.92) v3(170.54,19.94) v3(170.51,10.13) v3(170.59,12.17) v3(171.87,112.83) v3(171.81,107.3) v3(171.81,104.76) v3(171.81,102.22) v3(171.81,99.68) v3(171.81,97.49) v3(171.81,94.95) v3(171.81,92.41) v3(171.81,89.87) v3(171.81,87.33) v3(171.81,84.79) v3(171.81,82.25) v3(171.81,79.71) v3(171.81,77.17) v3(171.81,74.63) v3(171.81,72.09) v3(171.81,69.55) v3(171.81,67.01) v3(171.81,64.47) v3(171.81,61.93) v3(171.81,59.39) v3(171.81,56.85) v3(171.81,54.31) v3(171.81,49.23) v3(171.81,46.69) v3(171.81,44.15) v3(171.86,41.68) v3(171.86,39.14) v3(171.86,36.6) v3(171.86,34.06) v3(171.86,31.52) v3(171.86,28.98) v3(171.86,26.44) v3(171.86,23.9) v3(171.86,21.36) v3(171.86,18.82) v3(171.86,13.74) v3(171.86,11.2) v3(171.83,8.92) v3(171.83,6.38) v3(171.83,3.84) v3(171.83,1.3) v3(171.93,111.13) v4(9.25,76.48) v4(9.25,75.46) v4(9.25,74.45) v4(10.26,76.48) v4(10.26,75.46) v4(10.26,74.45) v4(11.28,76.48) v4(11.28,75.46) v4(11.28,74.45) v4(13.89,76.56) v4(30.97,89.08) v4(30.97,87.88) v4(31.47,88.48) v4(31.97,87.88) v4(32.67,107.53) v4(32.67,106.33) v4(32.88,97.64) v4(32.88,96.44) v4(33.17,106.93) v4(33.38,97.04) v4(33.67,106.33) v4(33.88,96.44) v4(38.54,65.62) v4(38.54,64.42) v4(39.04,65.02) v4(39.54,64.42) v4(51.97,81.44) v4(51.97,80.74) v4(51.97,80.04) v4(51.97,79.34) v4(51.97,78.64) v4(52.67,81.44) v4(52.67,80.74) v4(52.67,80.04) v4(52.67,79.34) v4(52.67,78.64) v4(53.37,81.44) v4(53.37,80.74) v4(53.37,80.04) v4(53.37,79.34) v4(53.37,78.64) v4(54.07,81.44) v4(54.07,80.74) v4(54.07,80.04) v4(54.07,79.34) v4(54.07,78.64) v4(54.77,81.44) v4(54.77,80.74) v4(54.77,80.04) v4(54.77,79.34) v4(54.77,78.64) v4(65.94,110.52) v4(66.01,108.71) v4(65.99,106.63) v4(66.04,104.52) v4(66.01,102.59) v4(65.99,100.66) v4(66.01,98.2) v4(72.35,95.38) v4(72.35,94.62) v4(72.35,93.85) v4(72.35,93.09) v4(72.35,92.33) v4(73.24,95.38) v4(73.24,94.62) v4(73.24,93.85) v4(73.24,93.09) v4(73.24,92.33) v4(74.13,95.38) v4(74.13,94.62) v4(74.13,93.85) v4(74.13,93.09) v4(74.13,92.33) v4(75.64,94.46) v4(75.69,92.46) v4(77.88,92.46) v4(77.9,94.49) v4(79.46,95.38) v4(79.46,94.62) v4(79.46,93.85) v4(79.46,93.09) v4(79.46,92.33) v4(80.35,95.38) v4(80.35,94.62) v4(80.35,93.85) v4(80.35,93.09) v4(80.35,92.33) v4(81.24,95.38) v4(81.24,94.62) v4(81.24,93.85) v4(81.24,93.09) v4(81.24,92.33) v4(87.53,110.67) v4(87.5,108.59) v4(87.55,106.48) v4(87.53,104.55) v4(87.5,102.62) v4(87.53,100.15) v4(87.63,112.83) v4(88.86,113.16) v4(88.86,112.4) v4(88.86,111.63) v4(88.86,110.87) v4(88.86,110.11) v4(89.75,113.16) v4(89.75,112.4) v4(89.75,111.63) v4(89.75,110.87) v4(89.75,110.11) v4(89.87,102.59) v4(90.32,98.81) v4(90.64,113.16) v4(90.64,112.4) v4(90.64,111.63) v4(90.64,110.87) v4(90.64,110.11) v4(95.97,113.16) v4(95.97,112.4) v4(95.97,111.63) v4(95.97,110.87) v4(95.97,110.11) v4(96.86,113.16) v4(96.86,112.4) v4(96.86,111.63) v4(96.86,110.87) v4(96.86,110.11) v4(97.75,113.16) v4(97.75,112.4) v4(97.75,111.63) v4(97.75,110.87) v4(97.75,110.11) v4(107.44,113.16) v4(107.44,112.4) v4(107.44,111.63) v4(107.44,110.87) v4(107.44,110.11) v4(108.33,113.16) v4(108.33,112.4) v4(108.33,111.63) v4(108.33,110.87) v4(108.33,110.11) v4(109.22,113.16) v4(109.22,112.4) v4(109.22,111.63) v4(109.22,110.87) v4(109.22,110.11) v4(114.55,113.16) v4(114.55,112.4) v4(114.55,111.63) v4(114.55,110.87) v4(114.55,110.11) v4(115.44,113.16) v4(115.44,112.4) v4(115.44,111.63) v4(115.44,110.87) v4(115.44,110.11) v4(116.33,113.16) v4(116.33,112.4) v4(116.33,111.63) v4(116.33,110.87) v4(116.33,110.11) v4(126.02,113.16) v4(126.02,112.4) v4(126.02,111.63) v4(126.02,110.87) v4(126.02,110.11) v4(126.91,113.16) v4(126.91,112.4) v4(126.91,111.63) v4(126.91,110.87) v4(126.91,110.11) v4(127.8,113.16) v4(127.8,112.4) v4(127.8,111.63) v4(127.8,110.87) v4(127.8,110.11) v4(133.13,113.16) v4(133.13,112.4) v4(133.13,111.63) v4(133.13,110.87) v4(133.13,110.11) v4(134.02,113.16) v4(134.02,112.4) v4(134.02,111.63) v4(134.02,110.87) v4(134.02,110.11) v4(134.91,113.16) v4(134.91,112.4) v4(134.91,111.63) v4(134.91,110.87) v4(134.91,110.11) v4(136.14,112.9) v4(136.27,111.25) v4(138.33,85.22) v4(142.53,95.38) v4(142.53,94.62) v4(142.53,93.85) v4(142.53,93.09) v4(142.53,92.33) v4(143.42,95.38) v4(143.42,94.62) v4(143.42,93.85) v4(143.42,93.09) v4(143.42,92.33) v4(144.31,95.38) v4(144.31,94.62) v4(144.31,93.85) v4(144.31,93.09) v4(144.31,92.33) v4(149.64,95.38) v4(149.64,94.62) v4(149.64,93.85) v4(149.64,93.09) v4(149.64,92.33) v4(150.53,95.38) v4(150.53,94.62) v4(150.53,93.85) v4(150.53,93.09) v4(150.53,92.33) v4(151.42,95.38) v4(151.42,94.62) v4(151.42,93.85) v4(151.42,93.09) v4(151.42,92.33) v5(65.45,69.12) v5(65.45,67.12) v5(66.35,70.22) v5(66.35,66.02) v5(68.55,70.32) v5(68.55,65.92) v5(69.75,70.02) v5(69.75,66.22) v6(107.92,85.62) v6(107.94,84.29) v6(107.94,82.98) v6(107.94,81.66) v6(107.94,80.35) v6(107.94,79.03) v6(107.94,77.72) v6(109.26,84.29) v6(109.26,82.98) v6(109.26,81.66) v6(109.26,80.35) v6(109.26,79.03) v6(109.26,77.72) v6(110.57,85.61) v6(110.57,84.29) v6(110.57,82.98) v6(110.57,81.66) v6(110.57,80.35) v6(110.57,79.03) v6(110.57,77.72) v6(111.89,85.61) v6(111.89,84.29) v6(111.89,82.98) v6(111.89,81.66) v6(111.89,80.35) v6(111.89,79.03) v6(111.89,77.72) v6(113.2,85.61) v6(113.2,84.29) v6(113.2,82.98) v6(113.2,81.66) v6(113.2,80.35) v6(113.2,79.03) v6(113.2,77.72) v6(114.52,85.61) v6(114.52,84.29) v6(114.52,82.98) v6(114.52,81.66) v6(114.52,80.35) v6(114.52,79.03) v6(114.52,77.72) v6(115.83,85.61) v6(115.83,84.29) v6(115.83,82.98) v6(115.83,81.66) v6(115.83,80.35) v6(115.83,79.03) v6(115.83,77.72)
